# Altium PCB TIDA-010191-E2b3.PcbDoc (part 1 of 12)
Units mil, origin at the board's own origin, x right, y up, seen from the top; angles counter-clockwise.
Board outline 9842.52 x 9842.4 mil, 6 copper layers (Layer 1 - Top Layer, Layer 2 - GND Layer, Layer 3 - Signal, Layer 4 - Signal, Layer 5 - GND, Bottom Layer), stack 59.9 mil thick; 1178 components, 642 nets, 3329 pads, 2967 vias.
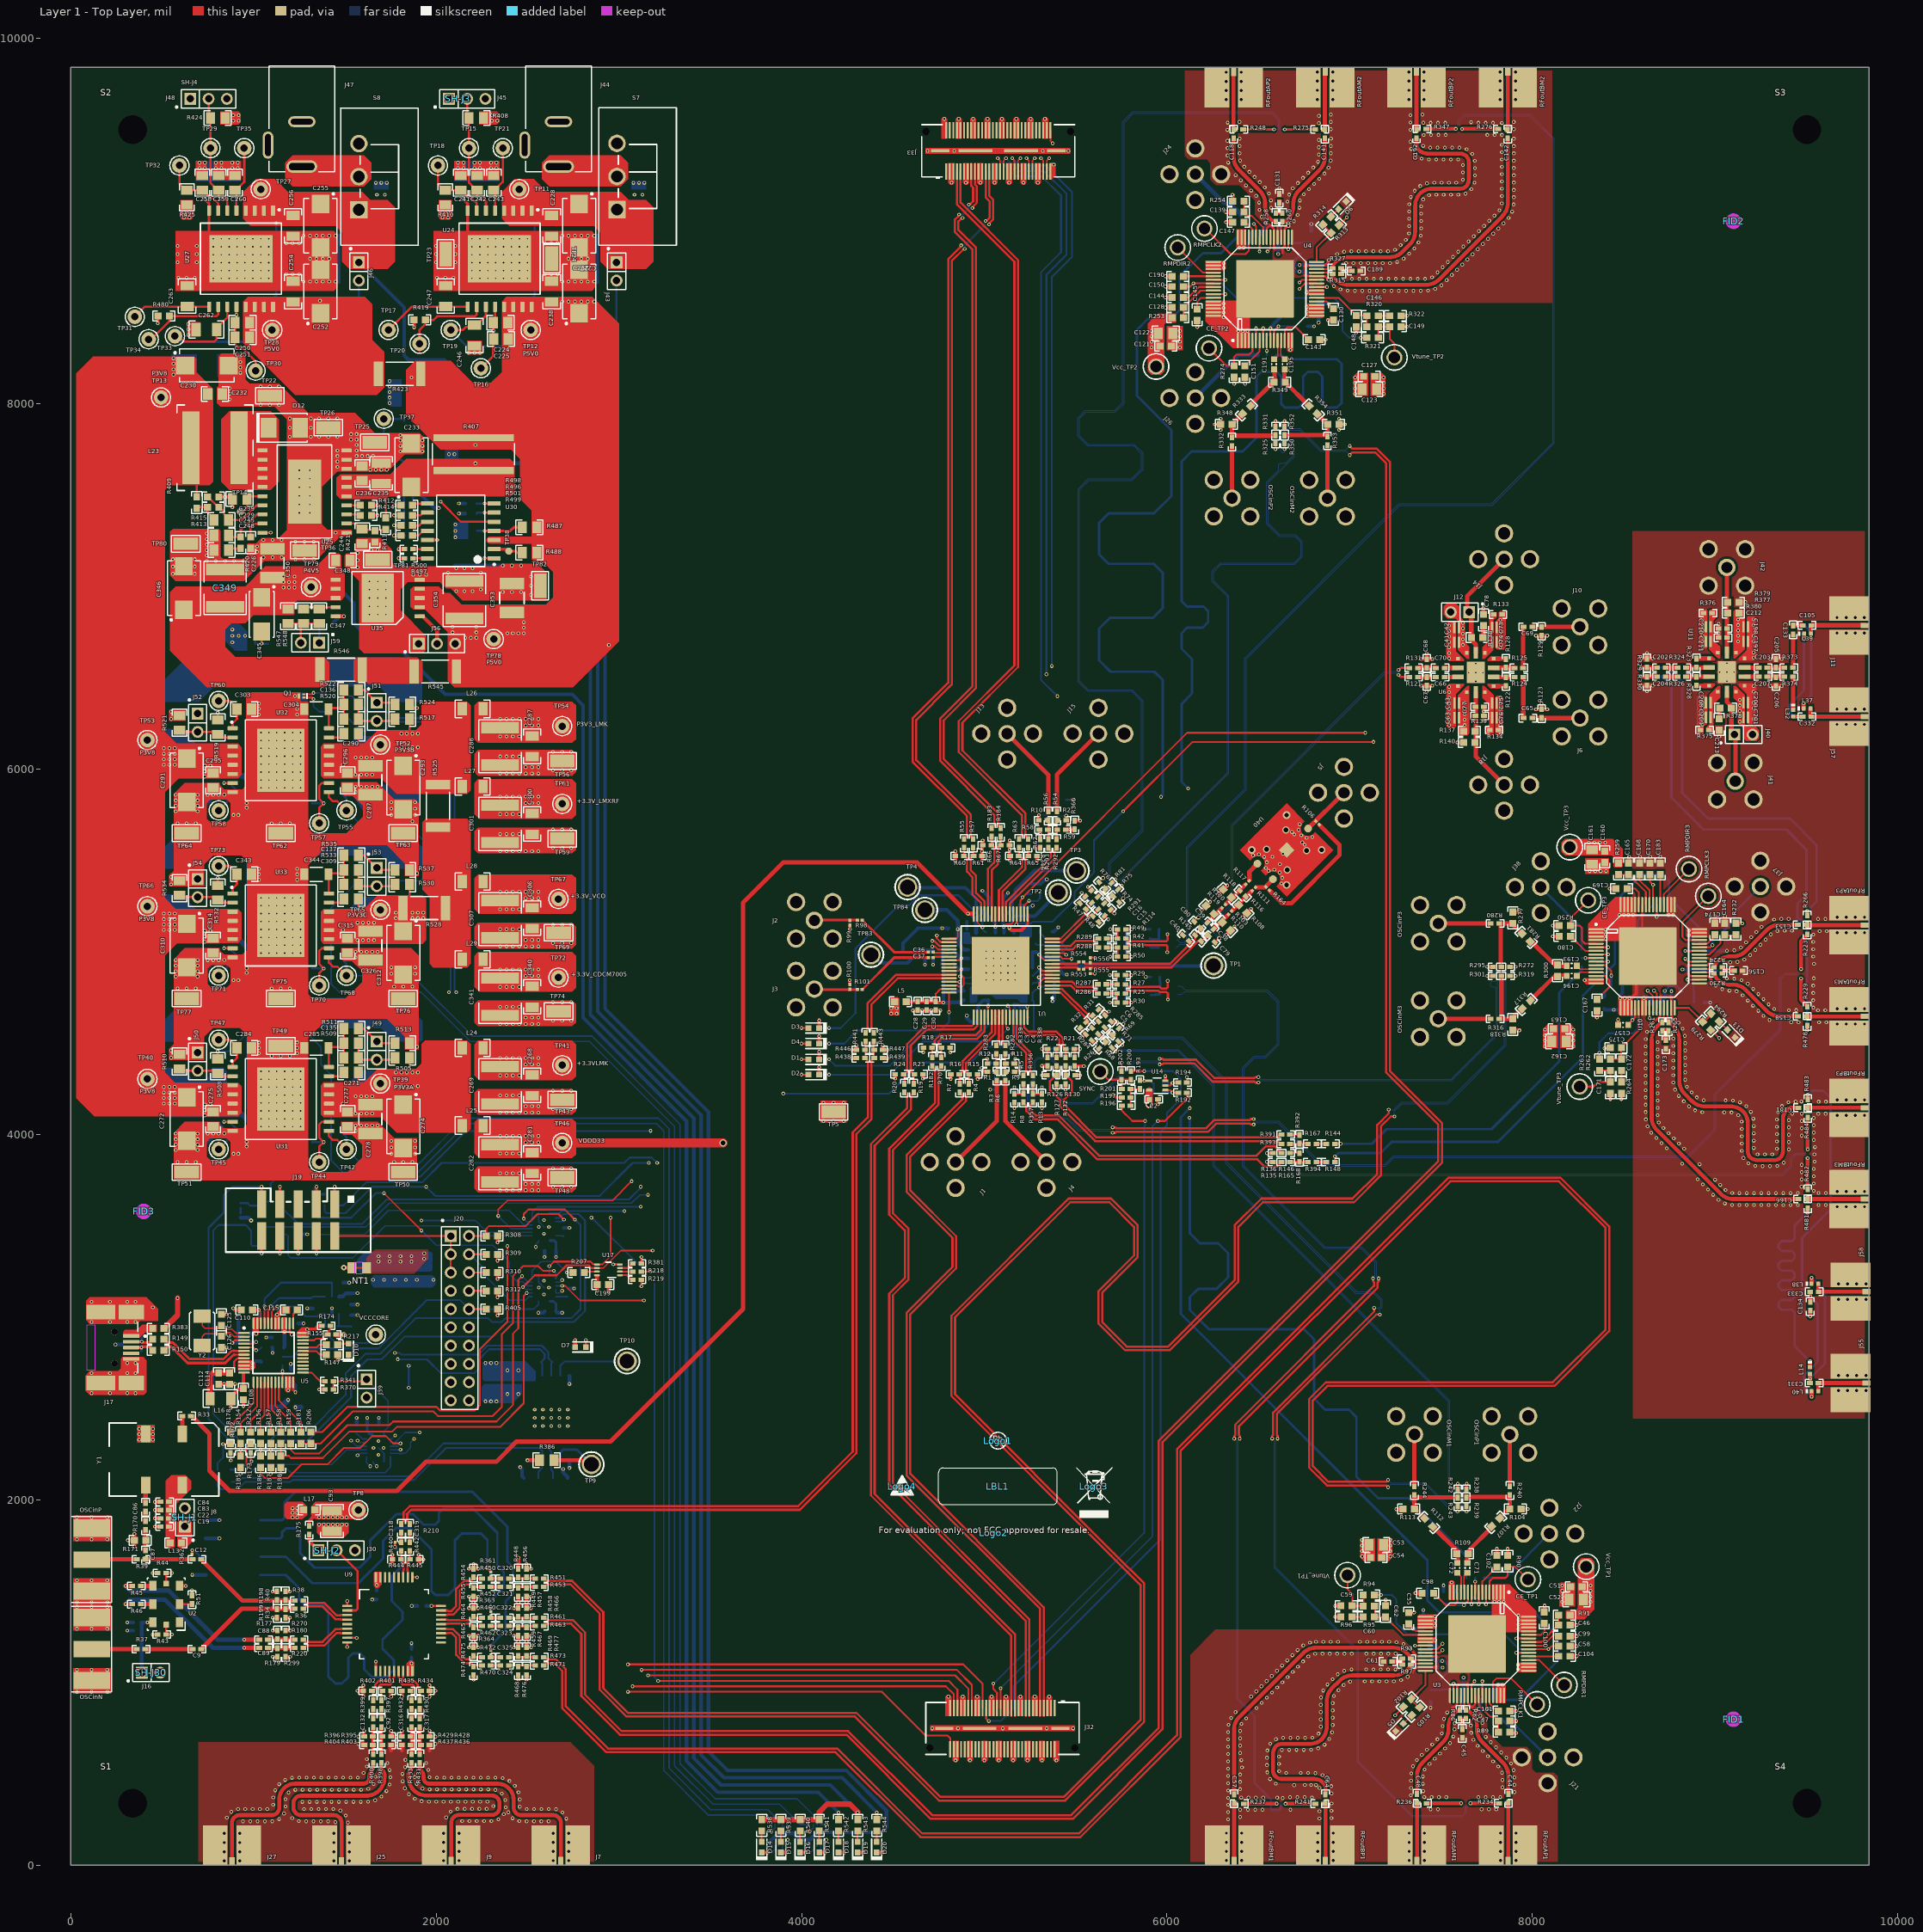
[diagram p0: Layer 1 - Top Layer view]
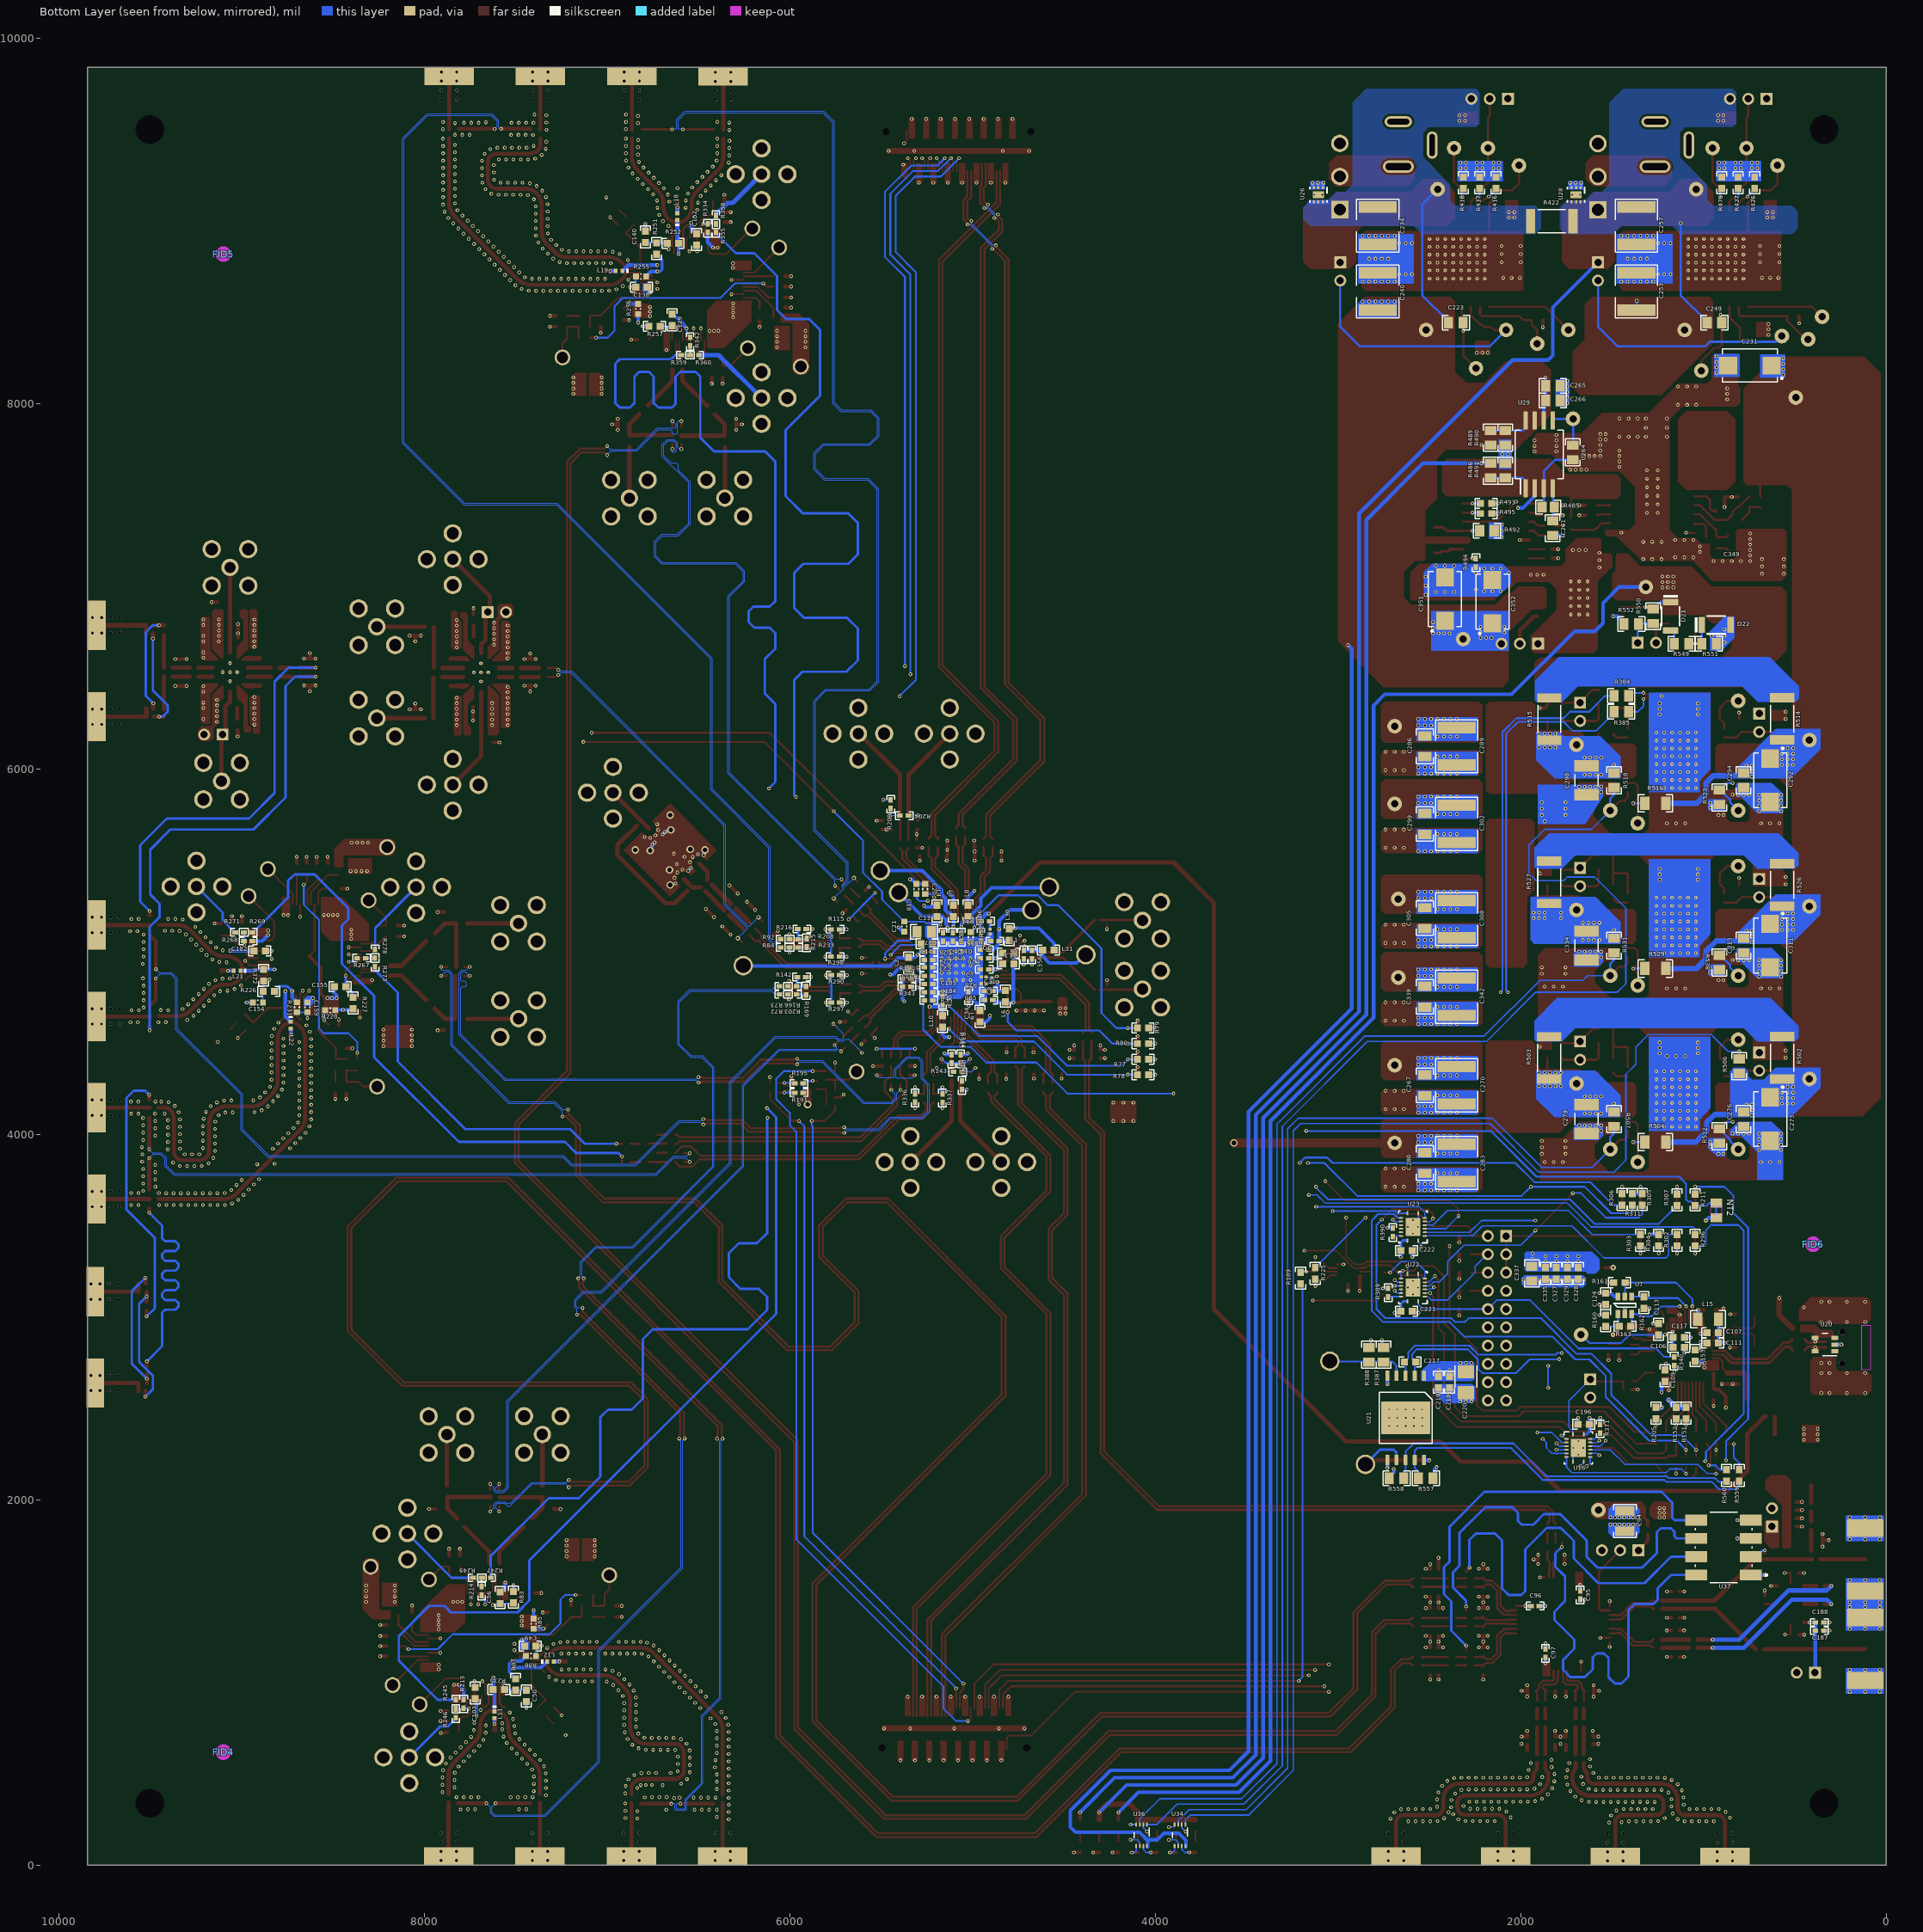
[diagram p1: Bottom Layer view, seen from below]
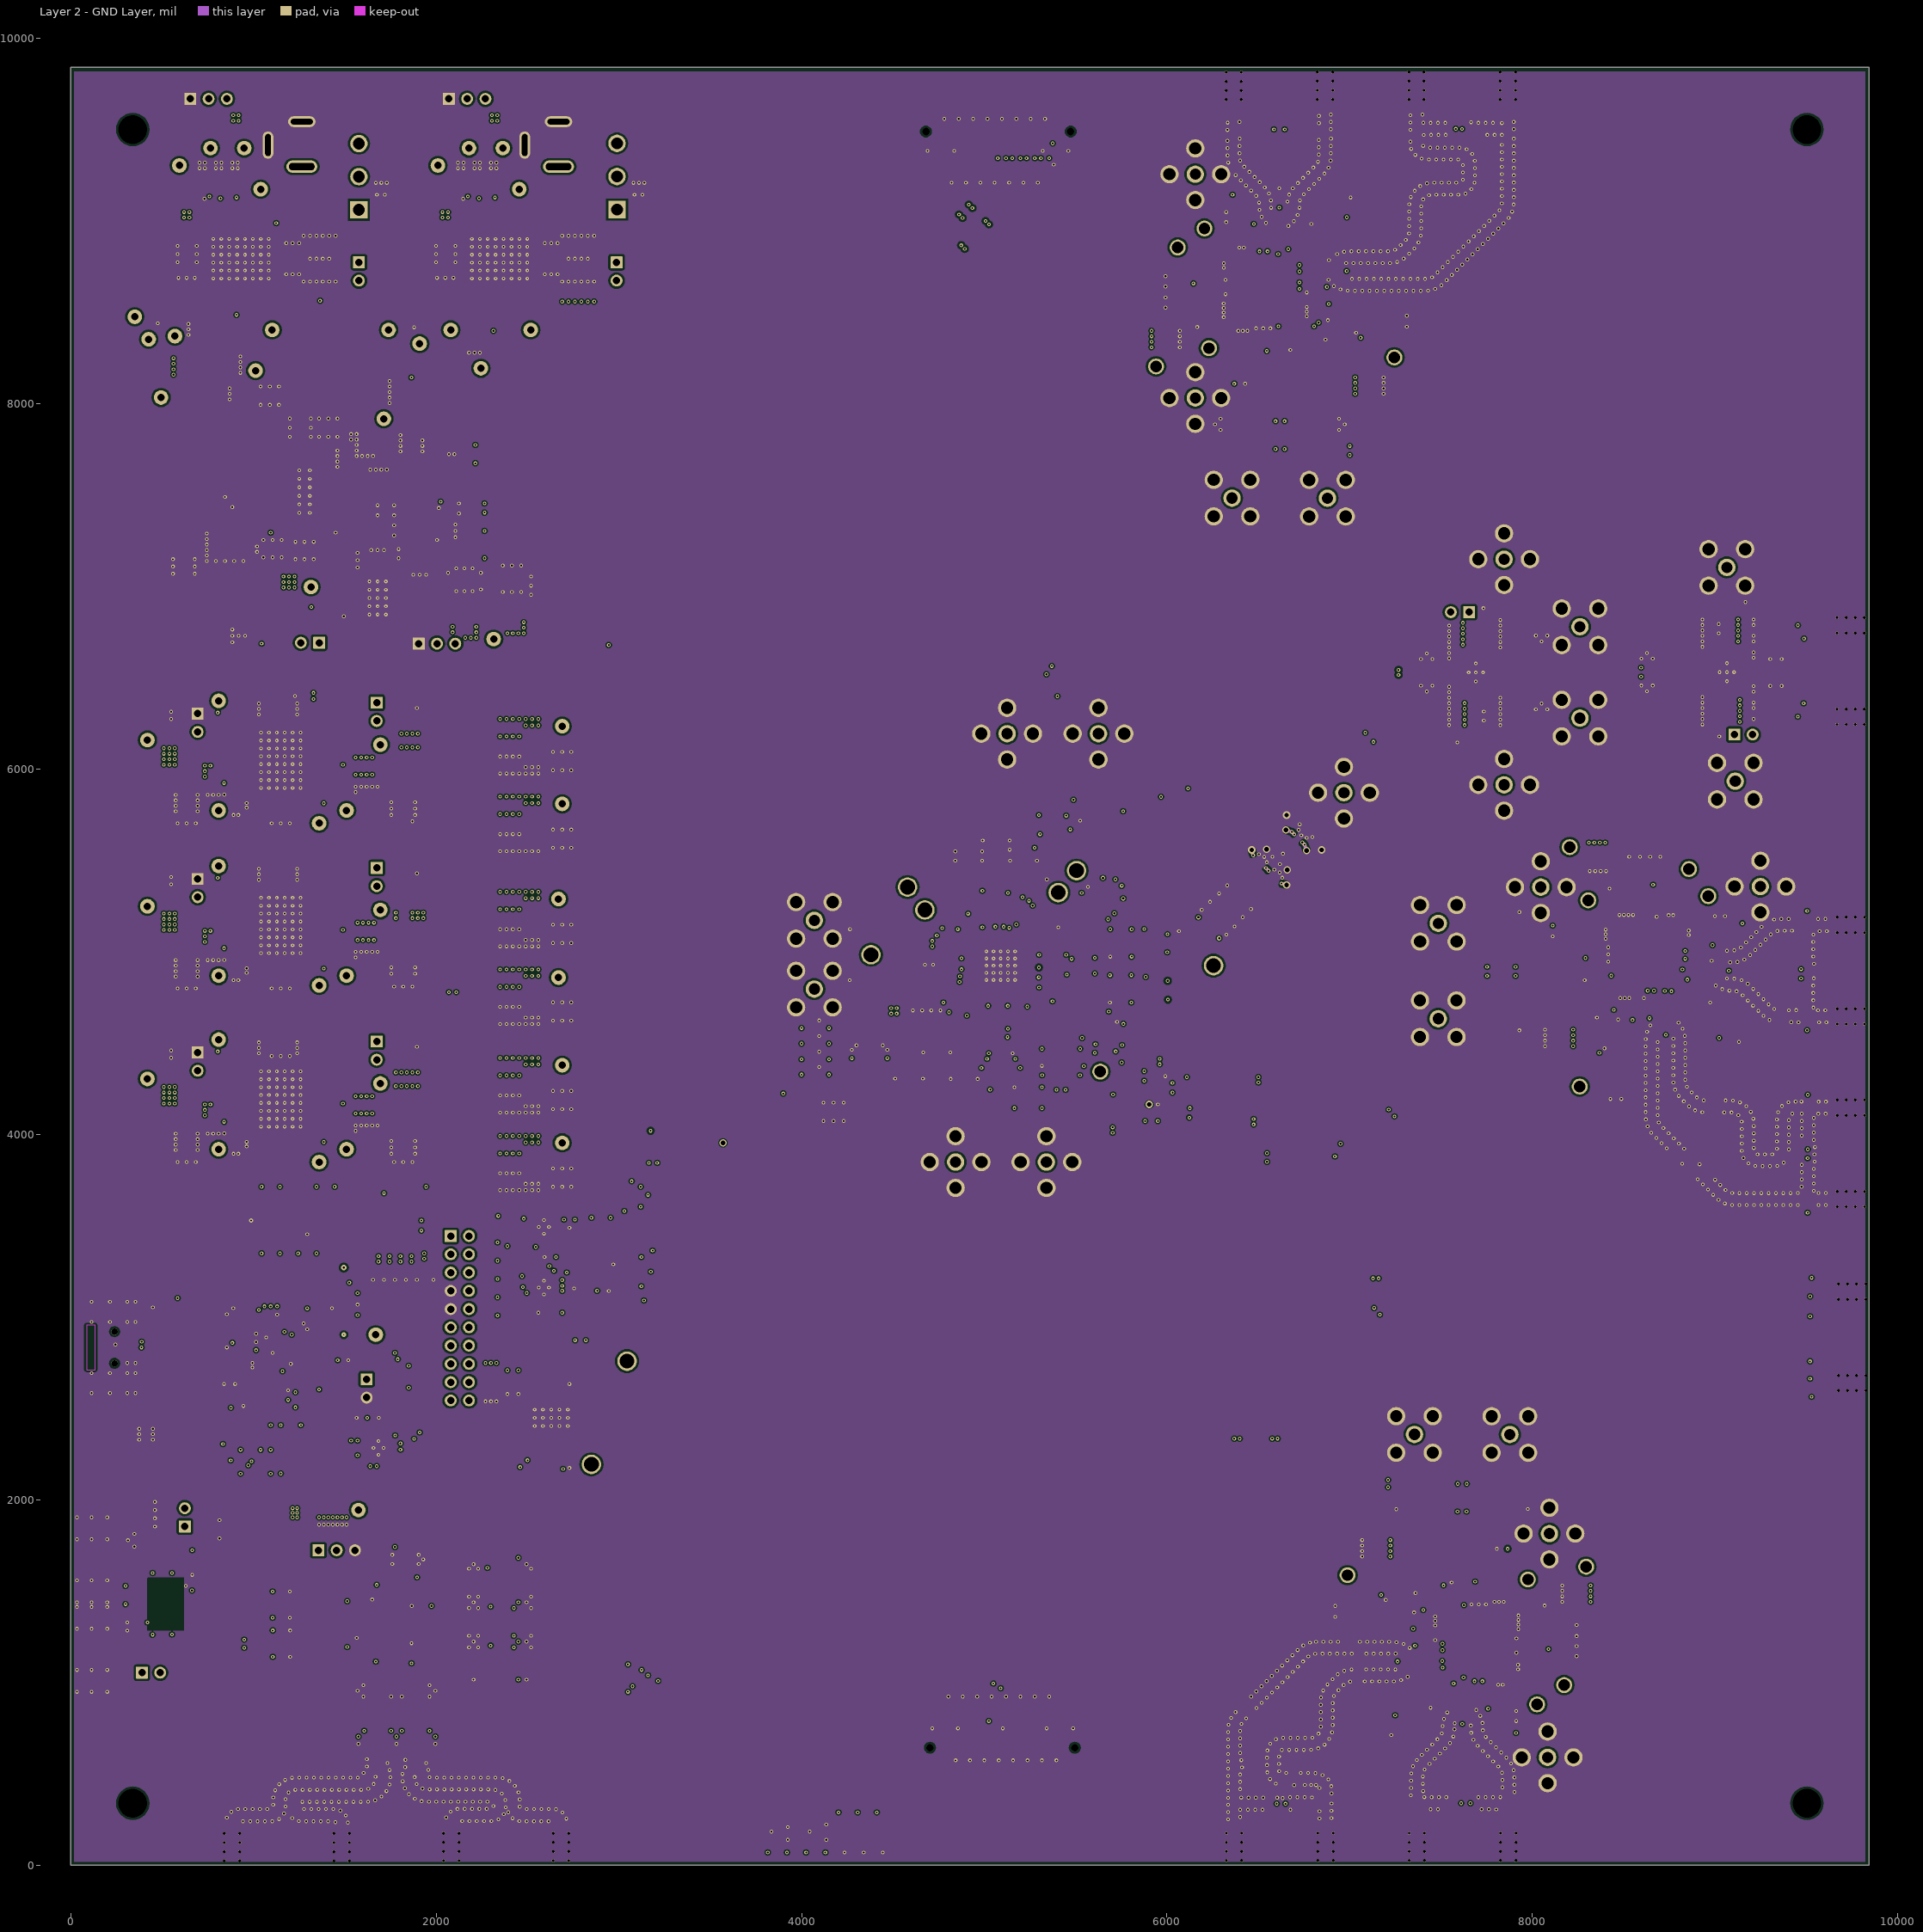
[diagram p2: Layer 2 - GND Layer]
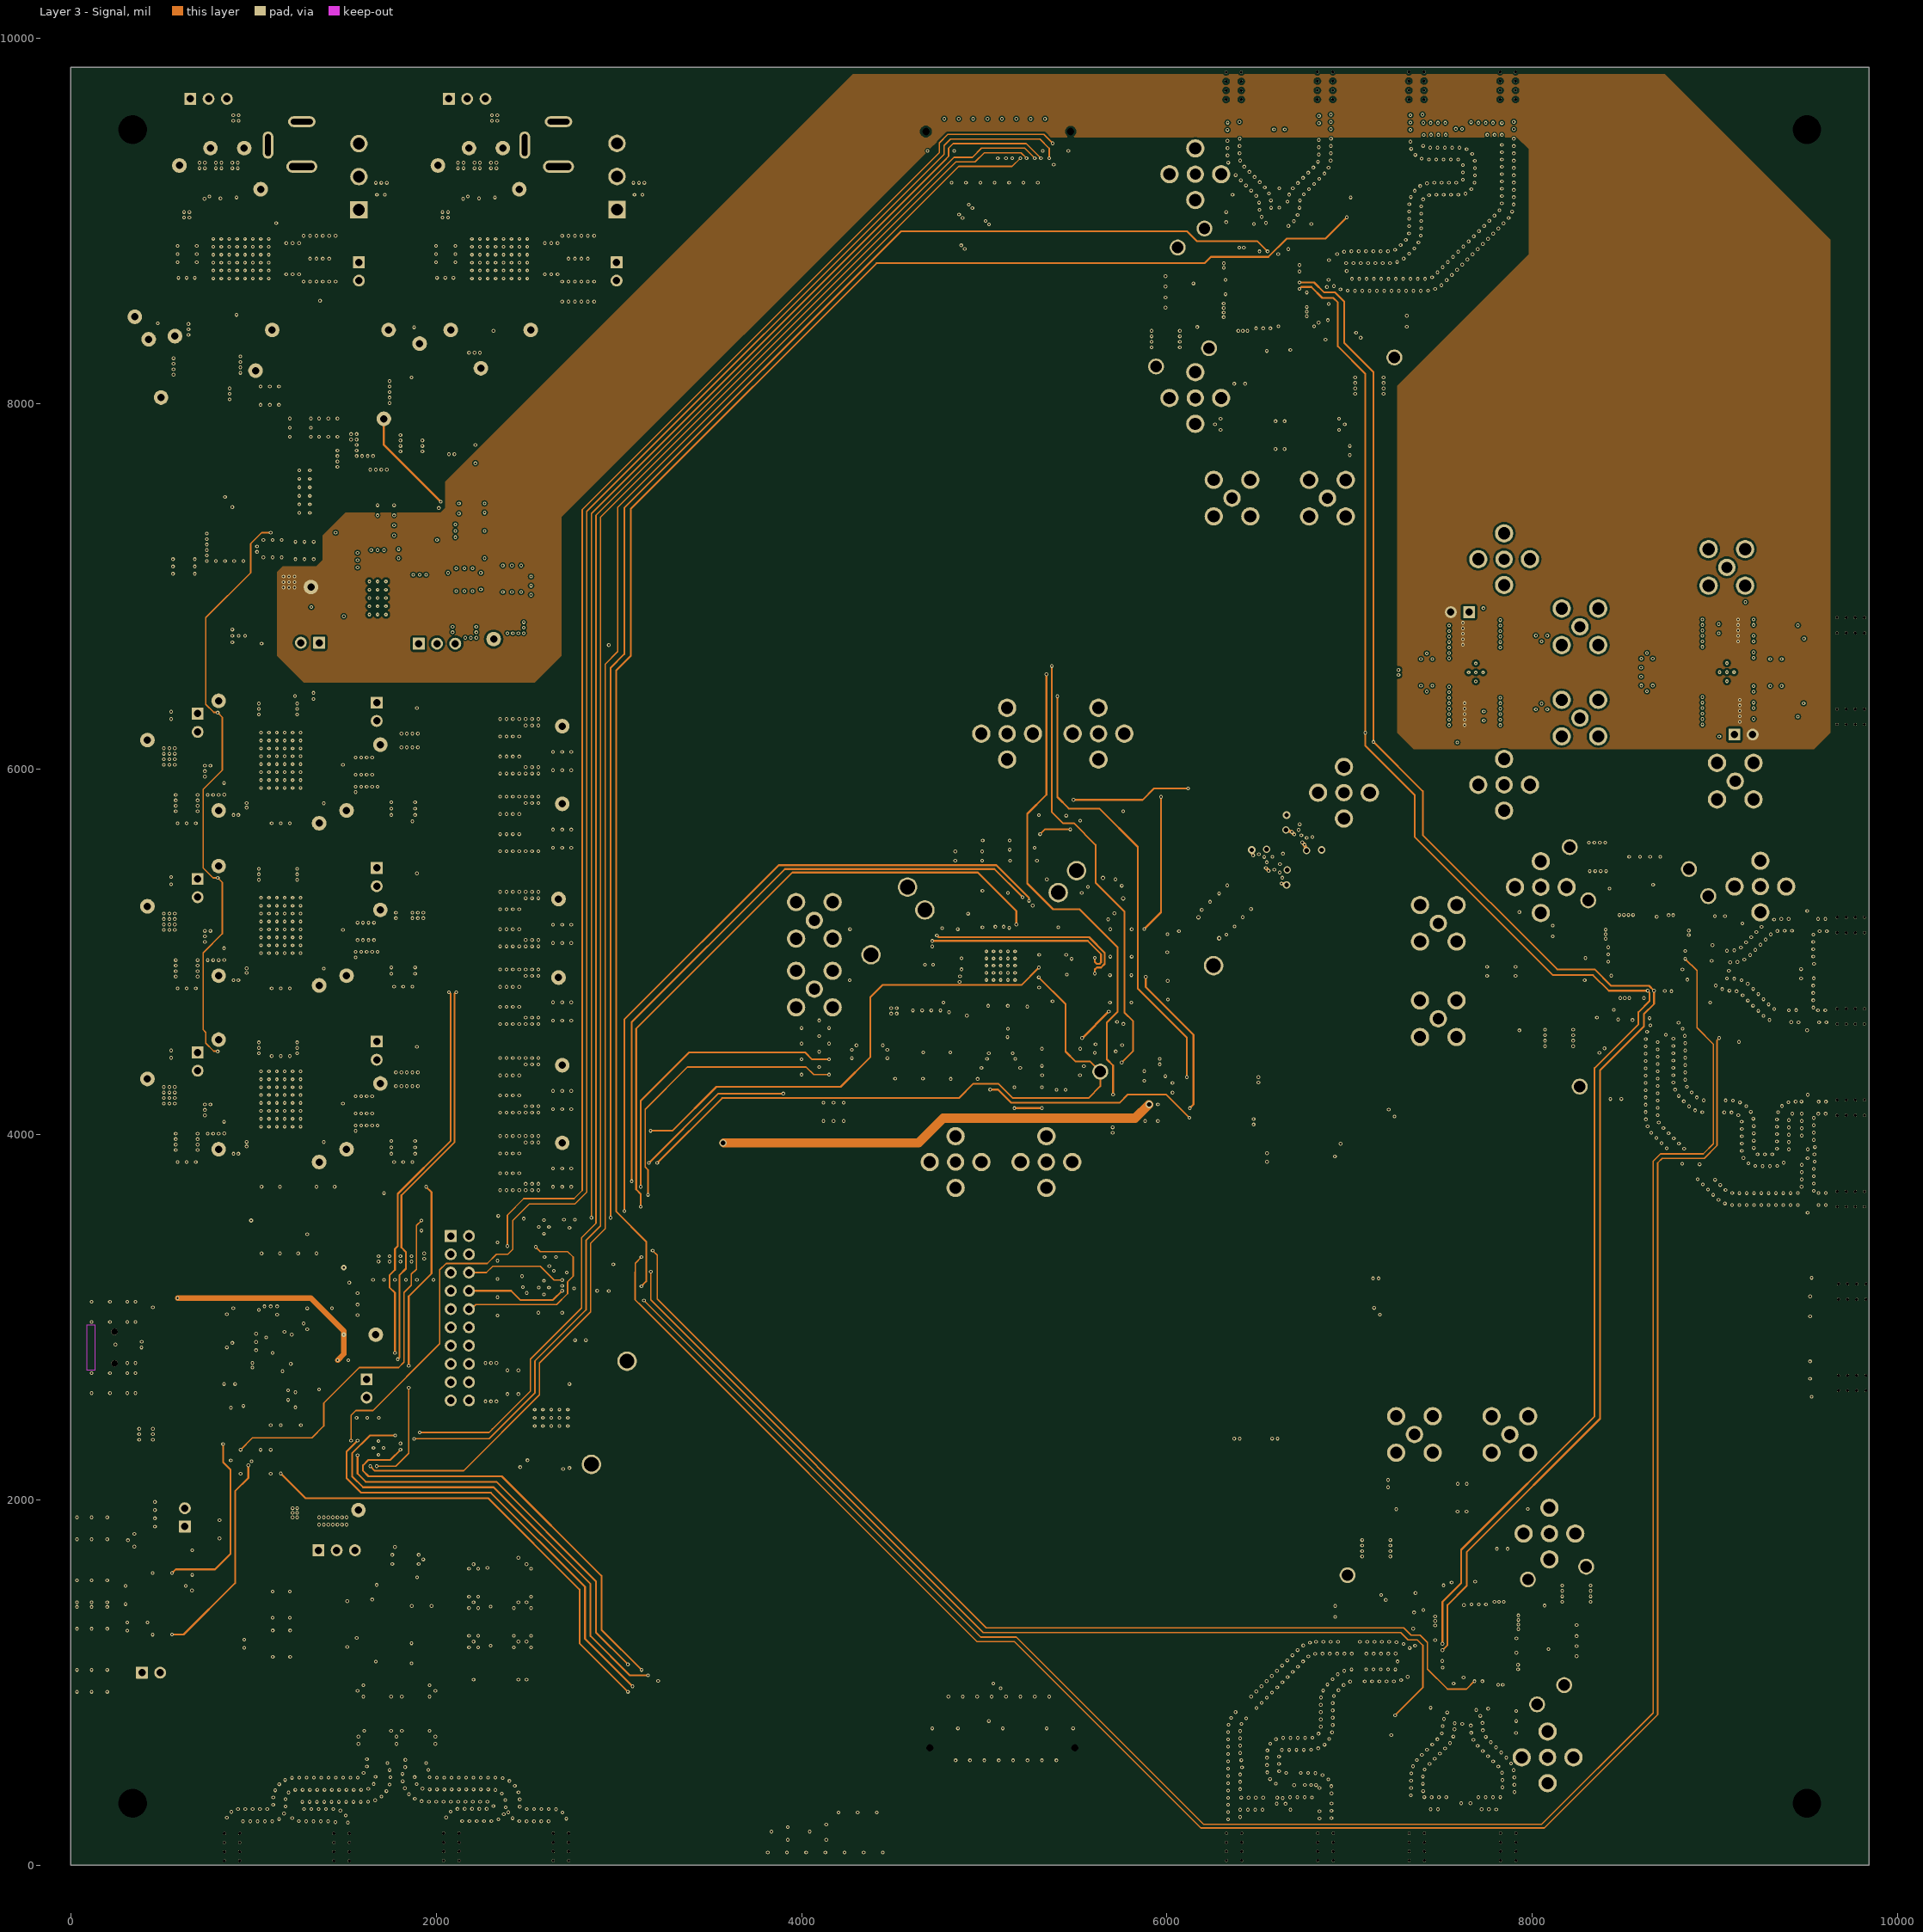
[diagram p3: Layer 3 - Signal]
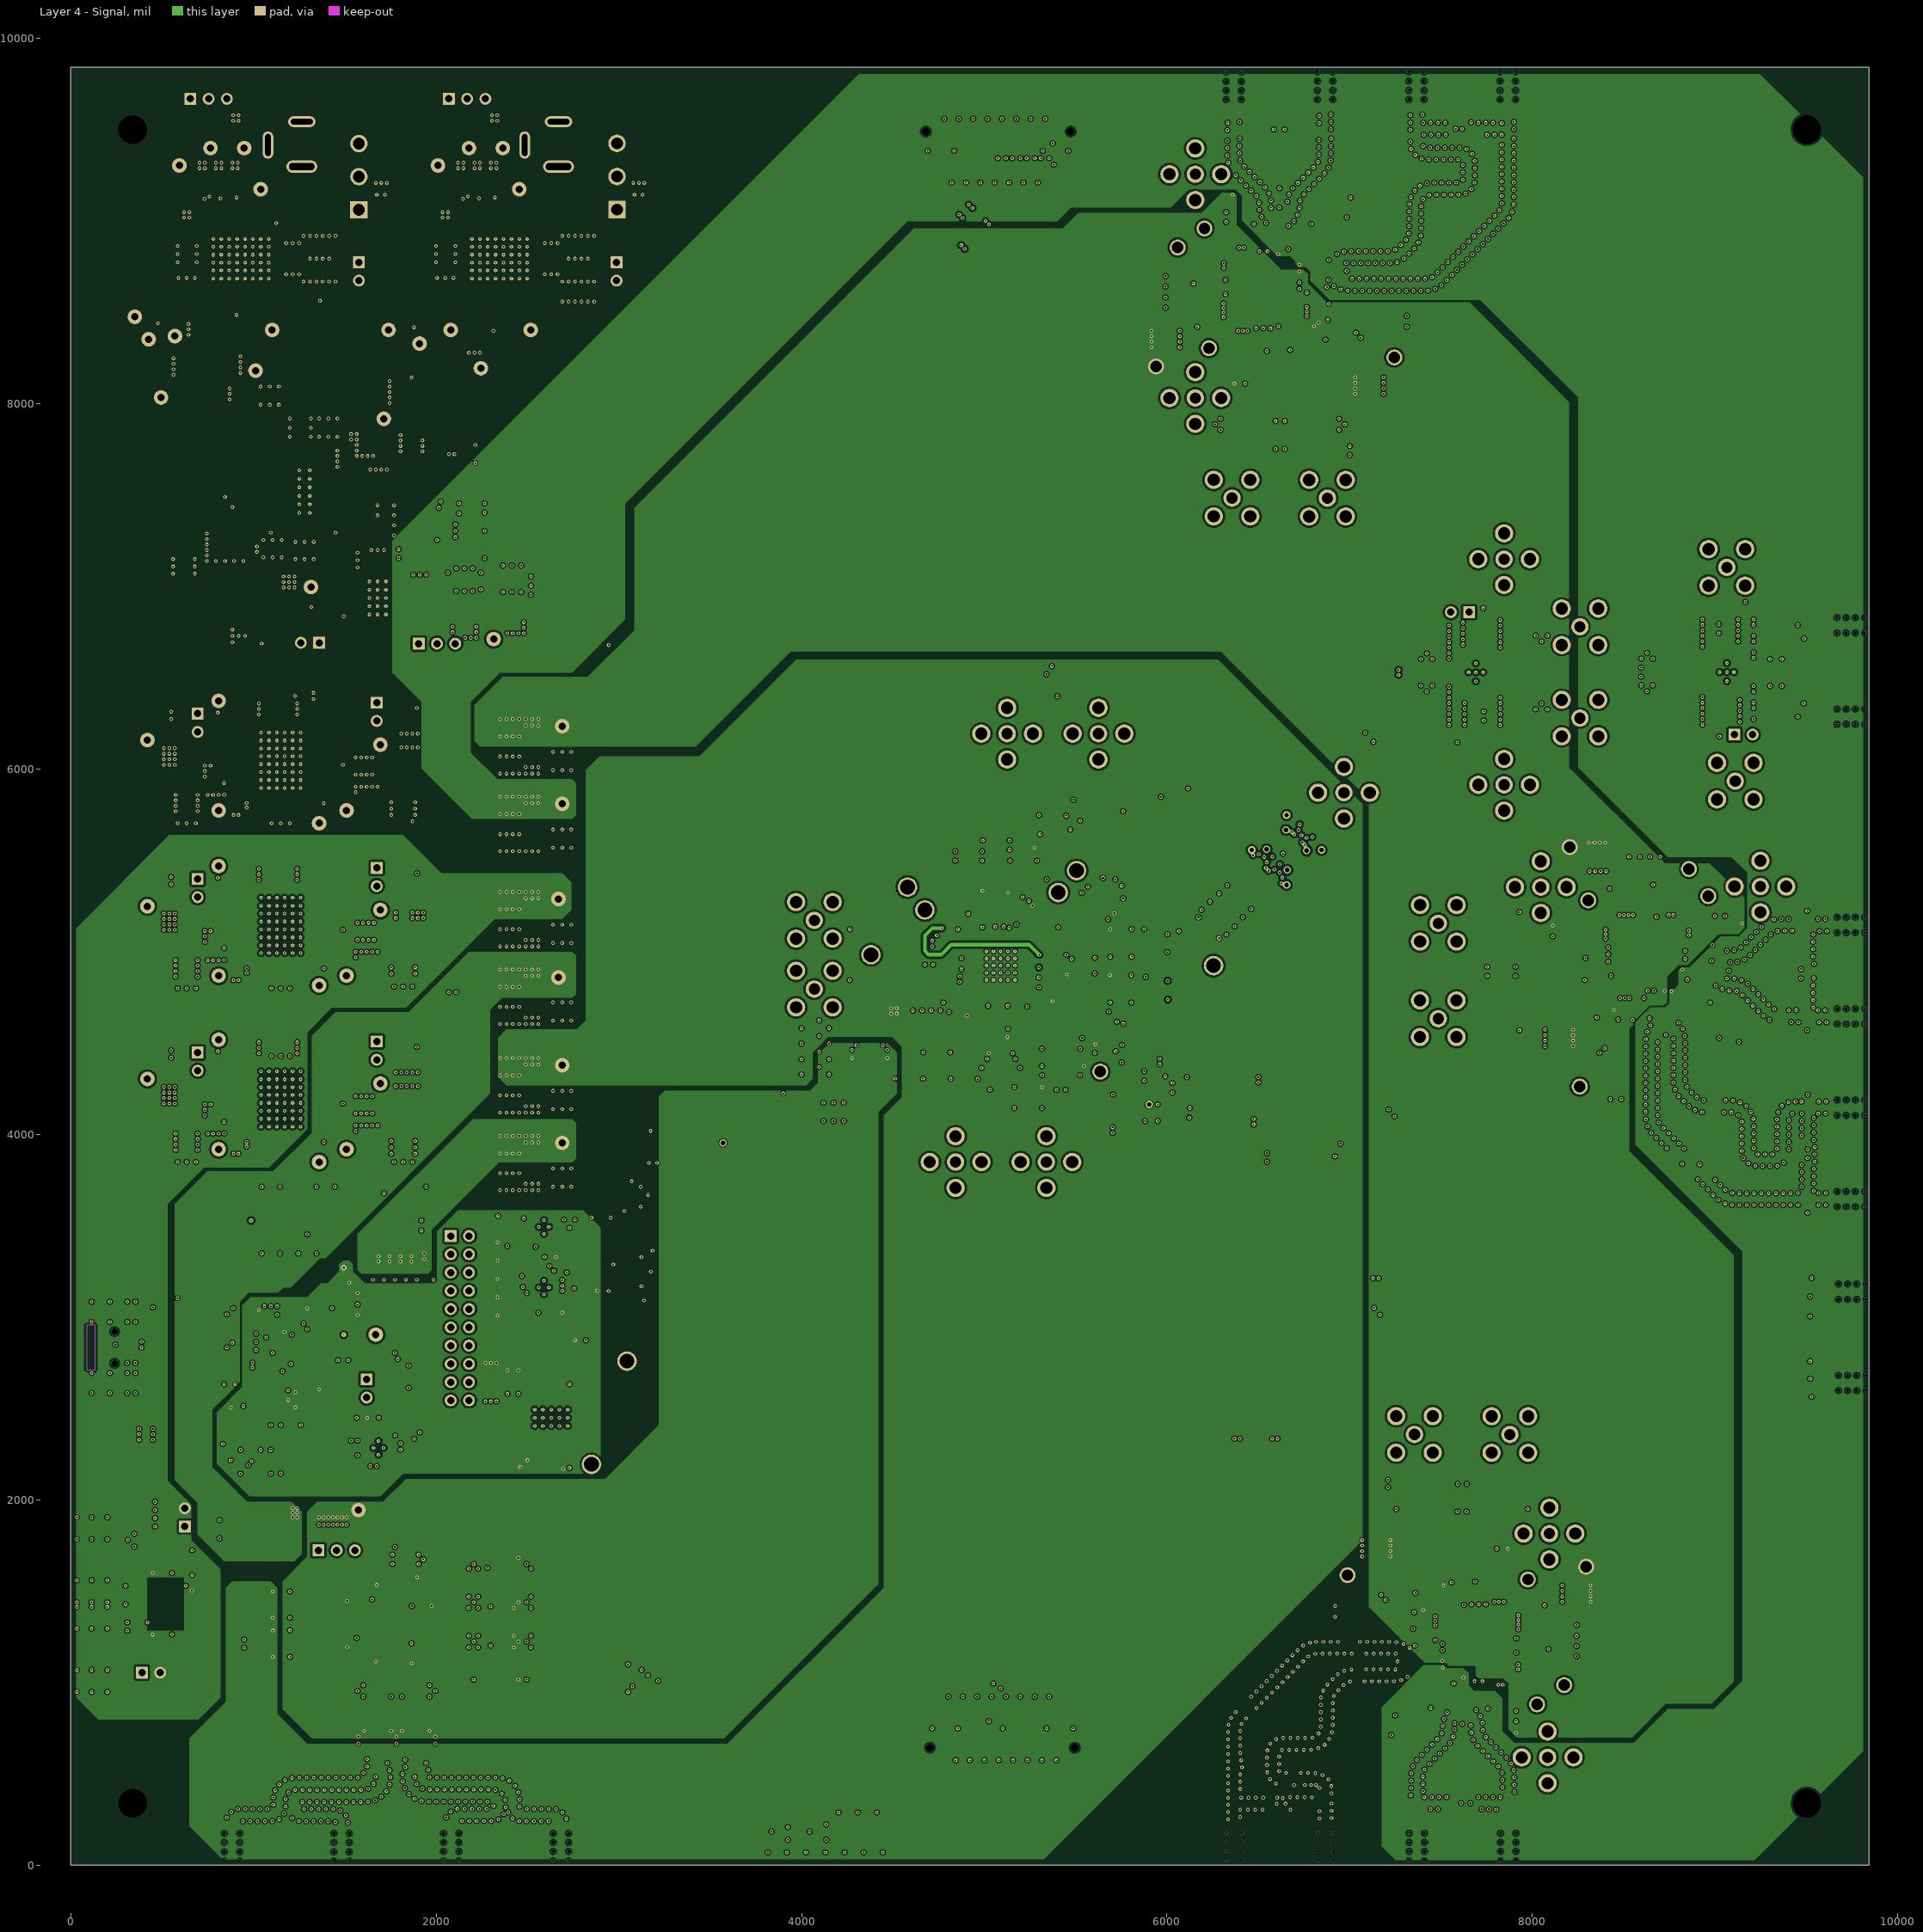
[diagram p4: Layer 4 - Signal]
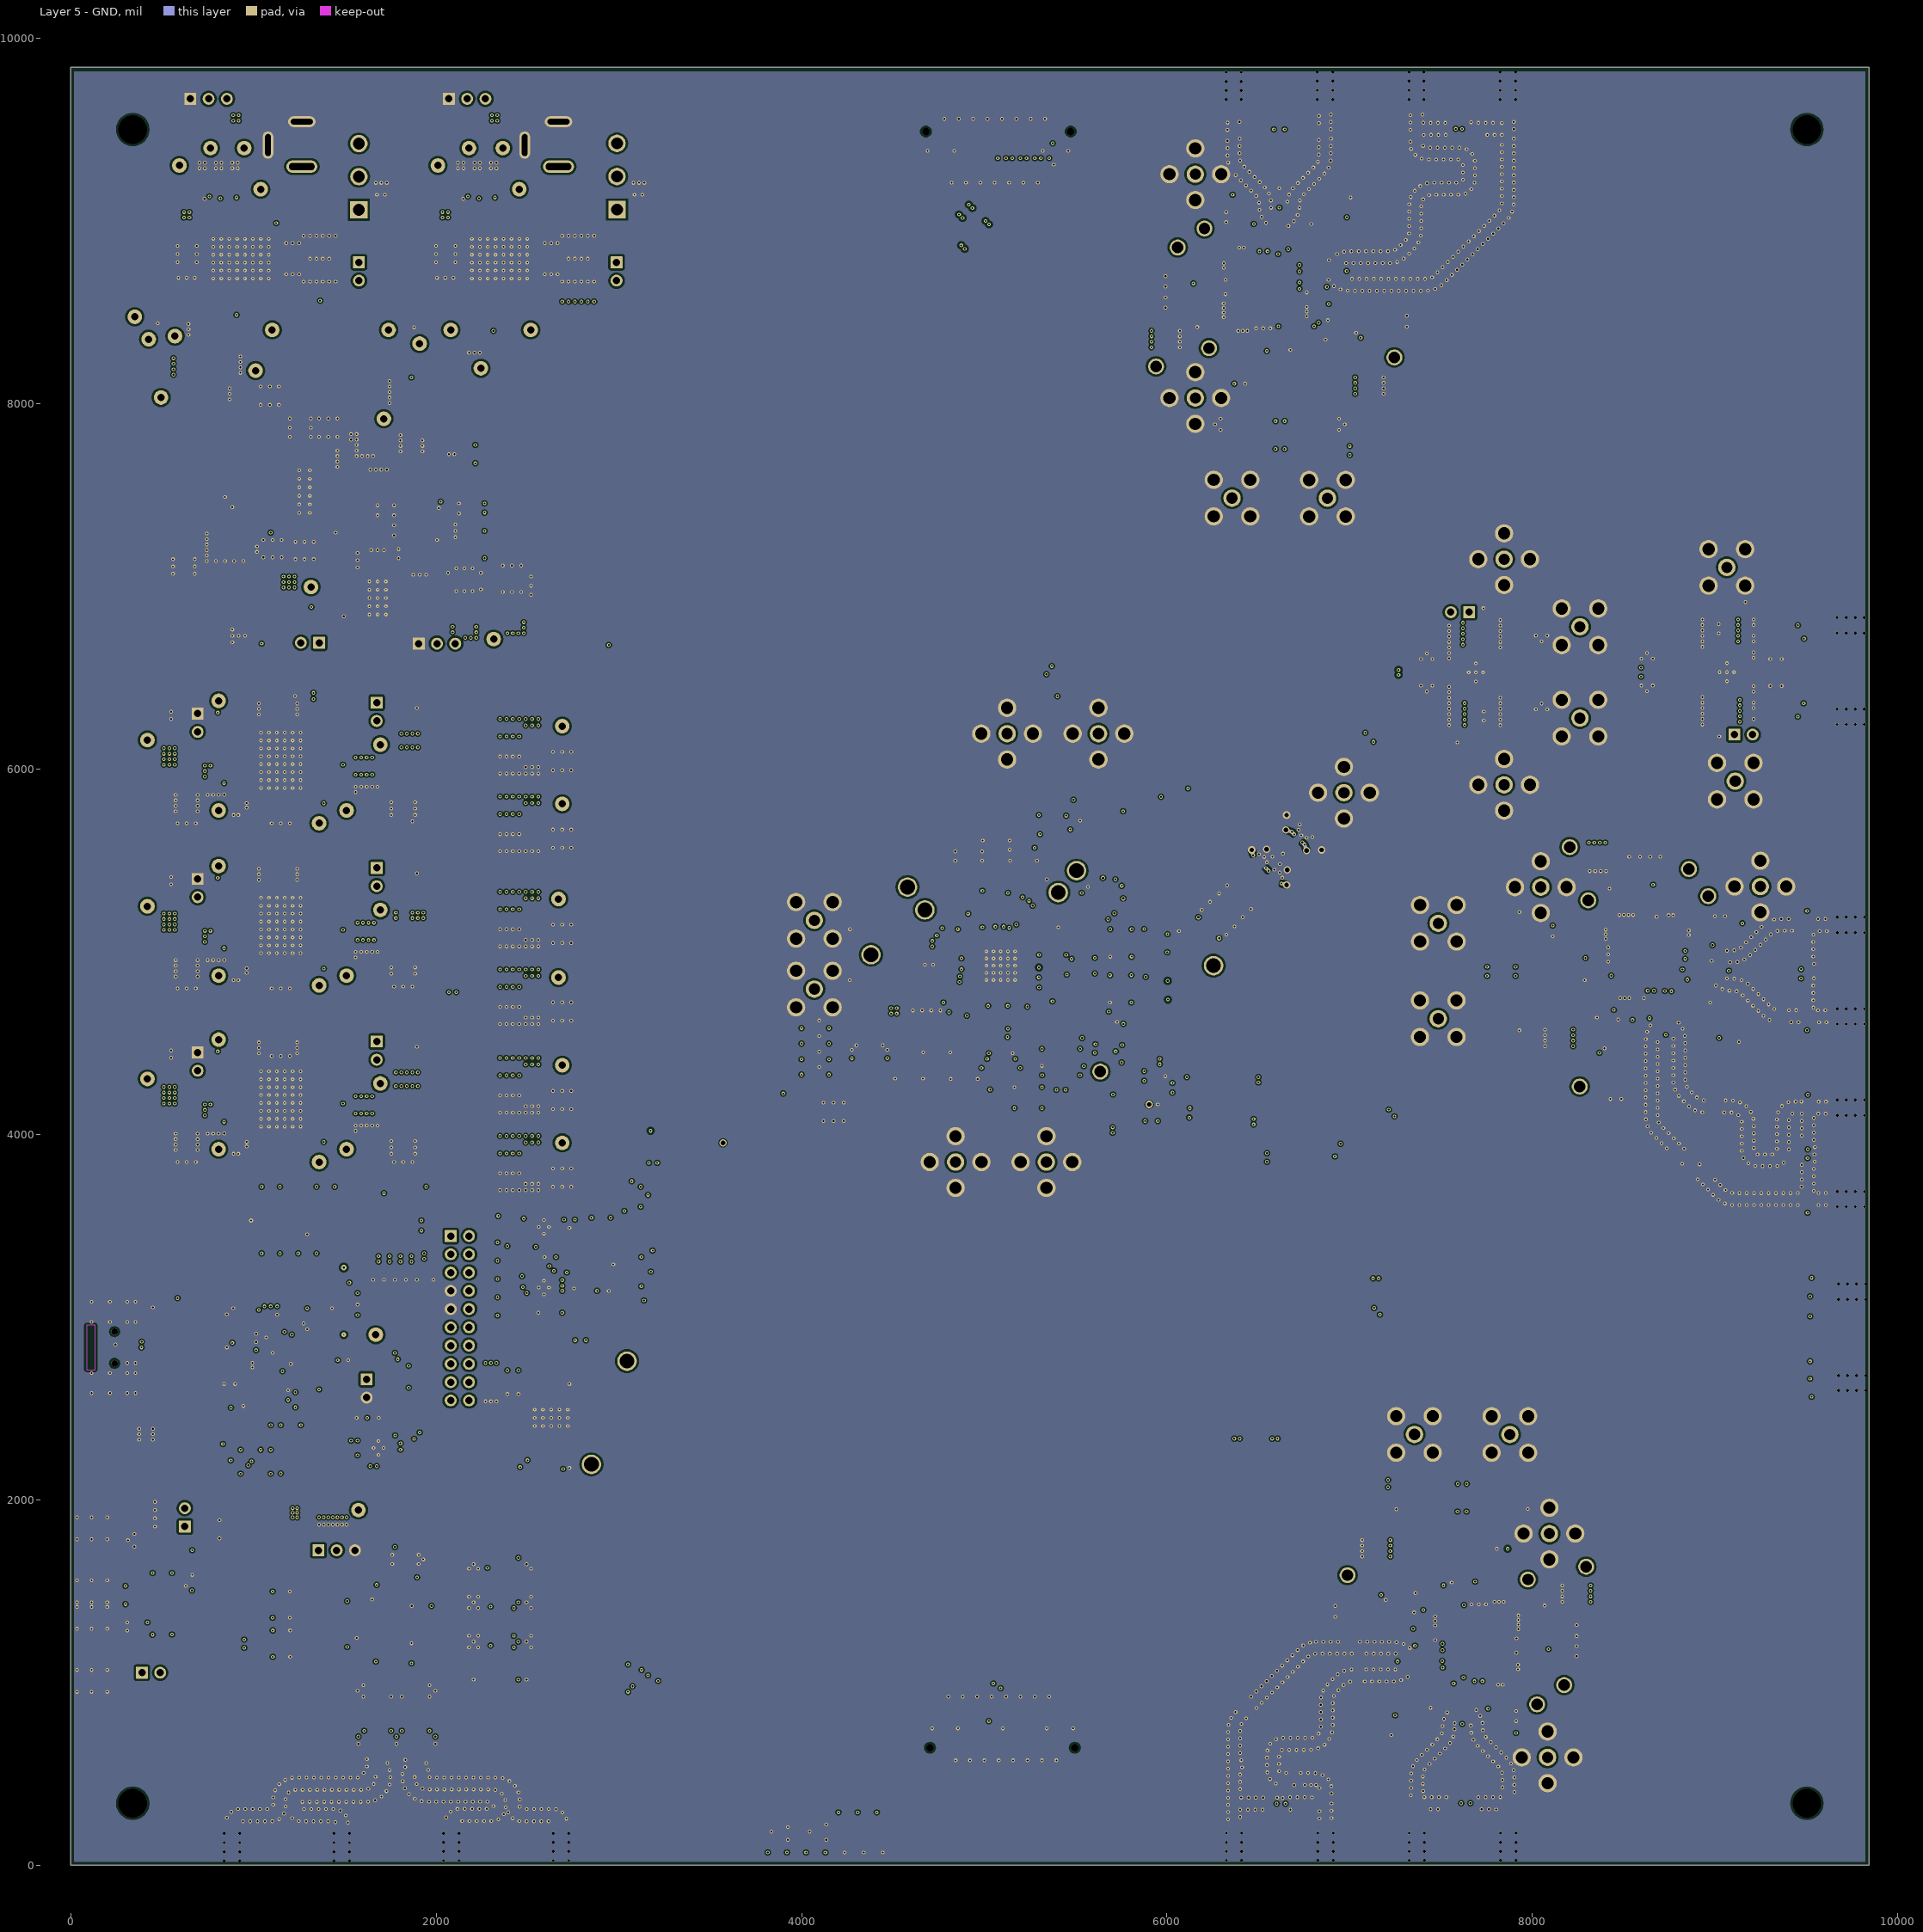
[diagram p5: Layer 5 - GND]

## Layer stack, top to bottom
Top Solder: solder mask 0.4, Solder Resist, Dk 3.5
Layer 1 - Top Layer: signal copper 1.4
Dielectric 1: core 12, Rogers4003C, Dk 4.2
Layer 2 - GND Layer: signal copper 1.4
Dielectric 2: prepreg 8.5, FR4 370, Dk 4.2
Layer 3 - Signal: signal copper 1.4
Dielectric 3: core 14.5, FR4 370, Dk 4.2
Layer 4 - Signal: signal copper 1.4
Dielectric 4: prepreg 8.5, FR4 370, Dk 4.2
Layer 5 - GND: signal copper 1.4
Dielectric 5: core 8, FR4 370, Dk 4.2
Bottom Layer: signal copper 1.4
Bottom Solder: solder mask 0.4, Solder Resist, Dk 3.5

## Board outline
0.09,0.12 0.09,9842.52 9842.61,9842.52 9842.61,0.12

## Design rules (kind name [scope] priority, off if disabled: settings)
AcuteAngle [All] p1: minimum=4.50000000000000E+0001 checktracksonly=FALSE
AssemblyTestPointUsage [All] p1: valid=2
Clearance [All vs not InComponent('FID1') and not InComponent('FID2') and not InComponent('FID3') and not InComponent('FID4') and not InComponent('FID5') and not InComponent('FID6') and not InComponent('U40')] p1: gap=7 ignorepadtopadclearanceinfootprint=TRUE except(3.75: Track-Track; 11.88: Arc-Poly Track-Poly SMDPad-Poly THPad-Poly Via-Poly Fill-Poly Poly-Poly)
ComponentClearance ComponentClearance_1 [HasFootprint('Keystone1573-2')] p1: gap=10 collisioncheckmode=3 verticalgap=10 showdistances=FALSE
ComponentClearance ComponentClearance_Shunt [InComponentClass('Header') vs InComponentClass('Shunt')] p2: gap=0 collisioncheckmode=3 verticalgap=0 showdistances=FALSE
ComponentClearance ComponentClearance_Logo [InComponentClass('Logo')] p3: gap=50 collisioncheckmode=3 verticalgap=10 showdistances=FALSE
ComponentClearance ComponentClearance_ScrewToNut [(HasFootprint('NY PMS 440 0025 PH')) vs (HasFootprint('Keystone_1902C'))] p4: gap=5 collisioncheckmode=3 verticalgap=10 showdistances=FALSE
ComponentClearance ComponentClearance_MountingHoles [InComponentClass('Mounting Holes')] p5: gap=250 collisioncheckmode=3 verticalgap=100000 showdistances=FALSE
ComponentClearance ComponentClearance_SmallPassives [HasFootprint('0201*') or HasFootprint('0402*') or HasFootprint('0508') or HasFootprint('0603*') or HasFootprint('0612') or HasFootprint('0805*') or HasFootprint('0815*') or HasFootprint('0830*') or HasFootprint('1206*') or HasFootprint('1210*') or HasFootprint('1808*') or HasFootprint('1812*') or HasFootprint('1825*') or HasFootprint('2010*') or HasFootprint('2220*') or HasFootprint('2225*') or HasFootprint('2512*') or HasFootprint('2728*') or HasFootprint('3518*') vs HasFootprint('0201*') or HasFootprint('0402*') or HasFootprint('0508') or HasFootprint('0603*') or HasFootprint('0612') or HasFootprint('0805*') or HasFootprint('0815*') or HasFootprint('0830*') or HasFootprint('1206*') or HasFootprint('1210*') or HasFootprint('1808*') or HasFootprint('1812*') or HasFootprint('1825*') or HasFootprint('2010*') or HasFootprint('2220*') or HasFootprint('2225*') or HasFootprint('2512*') or HasFootprint('2728*') or HasFootprint('3518*')] p6: gap=10 collisioncheckmode=3 verticalgap=10 showdistances=FALSE
ComponentClearance ComponentClearance_THtoSMT [IsThruComponent vs IsSMTComponent] p7: gap=40 collisioncheckmode=3 verticalgap=30 showdistances=FALSE
ComponentClearance ComponentClearance_THtoTH [IsThruComponent vs IsThruComponent] p8: gap=40 collisioncheckmode=3 verticalgap=30 showdistances=FALSE
ComponentClearance [All] p9: gap=20 collisioncheckmode=3 verticalgap=10 showdistances=FALSE
DiffPairsRouting DiffPairsRouting_100OHM [InDifferentialPairClass('100ohm')] p1: maxlimit=15 minlimit=4.25 mostfreqgap=8 toplayer_mingap=8 toplayer_minwidth=12 toplayer_maxwidth=12 toplayer_prefwidth=12 midlayer1_mingap=8 midlayer1_maxgap=8 midlayer1_minwidth=8 midlayer1_maxwidth=8 midlayer1_prefwidth=8 midlayer2_mingap=8 midlayer2_maxgap=8 midlayer2_minwidth=8 midlayer2_maxwidth=8 midlayer2_prefwidth=8 midlayer3_mingap=6.25 midlayer3_prefgap=6.25 midlayer3_minwidth=4.75 midlayer3_maxwidth=4.75 midlayer3_prefwidth=4.75 midlayer4_mingap=8 midlayer4_maxgap=8 midlayer4_minwidth=8 midlayer4_maxwidth=8 midlayer4_prefwidth=8 bottomlayer_prefgap=4.25 bottomlayer_minwidth=3.75 bottomlayer_maxwidth=3.75 bottomlayer_prefwidth=3.75 filterlayerstackid={EAC6E6AE-040B-479F-9AA2-99B4E561E951} maxuncoupledlength=500
DiffPairsRouting DiffPair_DiffPairsRouting_USB [InDifferentialPairClass('90ohm')] p2: maxlimit=15 minlimit=5 mostfreqgap=5 toplayer_mingap=7 toplayer_prefgap=7 toplayer_minwidth=8 toplayer_maxwidth=15 toplayer_prefwidth=15 midlayer1_mingap=7 midlayer1_maxgap=7 midlayer1_prefgap=7 midlayer1_minwidth=7 midlayer1_maxwidth=7 midlayer1_prefwidth=7 midlayer2_maxgap=5 midlayer2_minwidth=6.5 midlayer2_maxwidth=6.5 midlayer2_prefwidth=6.5 midlayer3_maxgap=5 midlayer3_minwidth=6.5 midlayer3_maxwidth=6.5 midlayer3_prefwidth=6.5 midlayer4_mingap=7 midlayer4_maxgap=7 midlayer4_prefgap=7 midlayer4_minwidth=7 midlayer4_maxwidth=7 midlayer4_prefwidth=7 bottomlayer_maxgap=5 bottomlayer_minwidth=7 bottomlayer_maxwidth=7 bottomlayer_prefwidth=7 maxuncoupledlength=500
FabricationTestPointUsage TestPointUsage [All] p1: valid=2 allowmultiple=FALSE
FabricationTestpoint Testpoint [All] p1: side=3 testpointundercomponent=TRUE minsize=40 maxsize=100 preferedsize=60 minholesize=0 maxholesize=40 preferedholesize=32 testpointgrid=1 allowsidetop=TRUE allowsidebottom=TRUE usegrid=TRUE gridtolerance=0.01
FanoutControl Fanout_LCC [IsLCC] p1: bgadir=Out bgaviamode=Centered fanoutstyle=Auto fanoutdirection=Alternating viagrid=1 // Fanout_LCC (Default Rule)
FanoutControl Fanout_BGA [IsBGA] p2: bgadir=Out bgaviamode=Centered fanoutstyle=Auto fanoutdirection=Alternating viagrid=1 // Fanout_BGA (Default Rule)
FanoutControl Fanout_Default [All] p4: bgadir=Out bgaviamode=Centered fanoutstyle=Auto fanoutdirection=Alternating viagrid=1 // Fanout_Default (Default Rule)
FanoutControl Fanout_Small [(CompPinCount < 5)] p5: bgadir=Out bgaviamode=Centered fanoutstyle=Auto fanoutdirection=OutThenIn viagrid=1 // Fanout_Small (Default Rule)
HoleSize [All] p1: absolutevalues=TRUE maxlimit=251 minlimit=7.87 maxpercent=80.000 minpercent=20.000
HoleToHoleClearance [All vs not InComponent('U40')] p1: gap=10 allowstackedmicrovias=TRUE
MatchedLengths u37_to_buffer_con [InNetClass('u37_buffer_con')] p1: tolerance=10 checknetsindiffpair=FALSE checkdiffpairvsdiffpair=TRUE checkxsignals=TRUE checkothers=TRUE
MatchedLengths LMK_LMX_DCLK [InxSignalClass('LMK_LMX_DCLK')] p2: tolerance=5 checknetsindiffpair=FALSE checkdiffpairvsdiffpair=TRUE checkxsignals=TRUE checkothers=TRUE
MatchedLengths LMK04832_FPGA [InxSignalClass('LMK04832_FPGA')] p3: tolerance=5 checknetsindiffpair=FALSE checkdiffpairvsdiffpair=TRUE checkxsignals=TRUE checkothers=TRUE
MatchedLengths FPGA_JESD [InxSignalClass('FPGA_JESD')] p4: tolerance=5 checknetsindiffpair=FALSE checkdiffpairvsdiffpair=TRUE checkxsignals=TRUE checkothers=TRUE
MatchedLengths DiffPair_MatchedLengths [InDifferentialPair ('BCLK')] p5: tolerance=1000 checknetsindiffpair=TRUE checkdiffpairvsdiffpair=FALSE checkxsignals=FALSE checkothers=FALSE
MinimumAnnularRing MinimumAnnularRing_ThermalPadVias [IsVia and InAnyComponent] p1: minimumring=5
MinimumAnnularRing [All] p2: minimumring=5
MinimumSolderMaskSliver MinimumSolderMaskSliver_Logo [InComponentClass('Logo') vs InComponentClass('Logo')] p1: minsoldermaskwidth=0.7
MinimumSolderMaskSliver [All] p2: minsoldermaskwidth=3.94
PlaneConnect [All] p1: planeconnectstyle=Relief reliefexpansion=10 reliefentries=4 reliefconductorwidth=10 reliefairgap=10
PolygonConnect [All] p1: connectstyle=Direct reliefconductorwidth=20 reliefentries=4 polygonreliefangle="90 Angle" airgapwidth=15
RoutingVias ThermalPadVias [IsVia and InAnyComponent] p1: holewidth=7.87 width=19.68 viastyle="Through Hole" minholewidth=7.87 minwidth=19.68 maxholewidth=25 maxwidth=42
RoutingVias [All] p2: holewidth=12 width=24 viastyle="Through Hole" minholewidth=7.87 minwidth=19.68 maxholewidth=26 maxwidth=42
SMDEntry [All] p1: side=TRUE corner=TRUE anyangle=FALSE
SMDToCorner [All] p1: distance=30000
SilkToSilkClearance [All] p1: silktosilkclearance=5
SilkToSolderMaskClearance SilkscreenOverComponentPads [IsPad] p1: minsilkscreentomaskgap=5 clearancetoexposedcopper=TRUE
SolderMaskExpansion [All] p1: expansion=2.5 istentingtop=FALSE
Width Width_PWR [InNetClass('PWR')] p1: maxlimit=100 minlimit=10 preferedwidth=20
Width [All] p2: maxlimit=100 minlimit=4.25 preferedwidth=10 toplayer_prefwidth=24 bottomlayer_prefwidth=13.5 minimp=50.000000 maximp=50.000000 favimp=50.000000 checkconnectedcopper=TRUE
15 further rules are at their usual default settings.

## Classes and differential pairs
net class NT2_Nets: GND IOVLVL
net class NT1_Nets: VDDD33 VREGIN
net class Y2_Nets: OSCI OSCO
net class Y1_Nets: GND NetC19_2 NetC86_1 NetR33_1
net class Vtune_TP3_Nets: NetC171_1
net class Vtune_TP2_Nets: NetC149_1
net class Vtune_TP1_Nets: NetC59_1
net class VCCCORE_Nets: NetC113_2
net class Vcc_TP3_Nets: P3V3_LMX
net class Vcc_TP2_Nets: P3V3_LMX
net class Vcc_TP1_Nets: P3V3_LMX
net class U40_Nets: GND NetJ5_1 NetR111_1 NetR117_1
net class U37_Nets: GND NetR210_2 NetR361_2 NetR362_2 NetR363_2 NetR364_2
net class U36_Nets: GND NetD16_2 NetD17_2 P5V0 PWRGD_LDO_B PWRGD_LDO_C
net class U35_Nets: GND NetC347_2 NetJ56_2 P4V5 P5V0
net class U34_Nets: GND NetD14_2 NetD15_2 P5V0 PWRGD PWRGD_LDO_A
net class U33_Nets: GND NetC137_2 NetC309_1 NetC343_1 NetJ54_2 NetR529_1 NetR536_2 P3V3C P3V8 PWRGD_LDO_C
net class U32_Nets: GND NetC136_2 NetC290_1 NetC303_1 NetJ52_2 NetR516_1 NetR523_2 P3V3B P3V8 PWRGD_LDO_B
net class U31_Nets: GND NetC135_2 NetC271_1 NetC284_1 NetJ50_2 NetR504_1 NetR512_2 P3V3A P3V8 PWRGD_LDO_A
net class U30_Nets: GND NetC264_2 NetR487_2 NetR488_2 NetR493_2 NetR494_2 NetR495_2 NetR496_2 NetR497_2 NetR498_2 NetR499_2 NetR500_2 NetR501_2 P5V0
net class U29_Nets: GND NetC261_1 NetC264_1 NetC264_2 NetR486_2 NetR489_2 NetU29_7 P5V0
net class U28_Nets: GND VIN_P5V0_Redundant
net class U27_Nets: GND NetC249_1 NetC250_1 NetC258_1 NetC259_1 NetC260_1 NetC262_2 NetC263_2 NetR480_2 VIN_P5V0_Redundant
net class U26_Nets: GND VIN_P5V0
net class U25_Nets: GND NetC226_2 NetC239_1 NetC244_1 NetC245_1 NetD12_1 NetR412_1 NetR414_1 P5V0* PWRGD VSENSE
net class U24_Nets: GND NetC223_1 NetC241_1 NetC242_1 NetC243_1 NetC246_2 NetC247_2 NetR419_2 P5V0 VIN_P5V0
net class U23_Nets: ACBUS0 ELMK_SCK ELMK_SDIO GND ILMK04832-SP_CSb ILMK_LMX_CLK ILMK_LMX_DATA LMK04832-SP_CSb LMK_LMX_CLK LMK_LMX_DATA LMK_SCSb NetR390_2 NetU23_12 NetU23_13 NetU23_14 VREGIN
net class U22_Nets: ACBUS0 ELMK_SDO GND ILMX1_CSb ILMX2_CSb ILMX_SDO LMX1_CSb LMX1_SCSb LMX2_CSb LMX2_SCSb LMX3_CSb LMX3_SCSb LMX_SDO NetR389_2 VREGIN
net class U21_Nets: GND NetC217_1 NetC217_2 NetR386_1 NetR387_1 NetR557_1 NetR558_1 VREGIN
net class U20_Nets: GND NetU20_1 NetU20_3 USB_N USB_P
net class U17_Nets: GND LMX1_CSb LMX2_CSb NetR207_1 NetR218_1 NetR219_1 NetR381_1 VREGIN
net class U16_Nets: ACBUS1 F_LMK_CSb F_LMK_LMX_CLK F_LMK_LMX_DATA FMC_SPI_CLK1 FMC_SPI_CLK2 FMC_SPI_SCSb1 FMC_SPI_SCSb3 FMC_SPI_SDIO1 FMC_SPI_SDIO2 GND LMK04832-SP_RESET1 LMK04832-SP_RESET2 NetR371_2 RESET VREGIN
net class U14_Nets: GND NetR191_1 NetR191_2 NetR194_2 VDDD33
net class U11_Nets: GND NetC203_2 NetC207_2 NetC208_2 NetC210_1 NetC212_1 NetJ40_1 NetR323_1 NetR323_2 NetR326_2 NetR328_2 P4V5
net class U10_Nets: ADC_CLK3+ ADC_CLK3- ADC_SYSREF3+ ADC_SYSREF3- GND LMK_LMX_CLK LMK_LMX_DATA LMX3_CSb LMX_OSCin3+ LMX_OSCin3- MUXout3 NetC154_2 NetC155_2 NetC157_2 NetC159_1 NetC164_2 NetC165_2 NetC167_2 NetC168_1 NetC169_2 NetC170_2 NetC172_1 NetC174_1 NetC180_1 NetC182_1 NetC183_1 NetCE_TP3_1 NetR267_1 NetR268_1 NetRMPCLK3_1 NetRMPDIR3_1
net class U9_Nets: C_VCC CDCLVP_CLK1_N CDCLVP_CLK1_P CDCM7005-SP_VCXO_IN_N CDCM7005-SP_VCXO_IN_P GND NetJ30_2 NetR397_1 NetR399_1 NetR430_1 NetR432_1 NetR440_1 NetR442_1 NetR450_1 NetR452_1 NetR460_1 NetR462_1 NetR470_1 NetR472_1 NetU9_11 NetU9_12 NetU9_19 NetU9_20 NetU9_31 NetU9_32 NetU9_33 NetU9_34 VBB
net class U7_Nets: EECLK EECS EEDATA GND NetR160_1 VREGIN
net class U6_Nets: GND NetC66_2 NetC70_2 NetC73_2 NetC75_1 NetC77_1 NetJ12_1 NetR122_1 NetR122_2 NetR125_2 NetR128_2 P4V5
net class U5_Nets: ADBUS0 ADBUS1 ADBUS2 ADBUS3 ADBUS4 ADBUS5 ADBUS6 ADBUS7 D_N D_P EECLK EECS EEDATA GND NetC113_2 NetR147_1 NetR153_1 NetR217_2 NetR340_2 NetR341_2 NetU5_26 NetU5_27 NetU5_28 NetU5_29 NetU5_30 NetU5_33 OSCI OSCO USB_RESET VCCA VPHY VPLL VREGIN
net class U4_Nets: ADC_CLK2+ ADC_CLK2- ADC_SYSREF2+ ADC_SYSREF2- GND LMK_LMX_CLK LMK_LMX_DATA LMX2_CSb LMX2_OSCin+ LMX2_OSCin- MUXout2 NetC128_2 NetC129_2 NetC130_2 NetC138_2 NetC139_2 NetC140_2 NetC143_2 NetC144_1 NetC145_2 NetC146_1 NetC147_1 NetC150_2 NetC151_1 NetC152_1 NetC190_1 NetCE_TP2_1 NetR334_1 NetR342_1 NetRMPCLK2_1 NetRMPDIR2_1
net class U3_Nets: ADC_CLK1+ ADC_CLK1- ADC_SYSREF1+ ADC_SYSREF1- GND LMK_LMX_CLK LMK_LMX_DATA LMX1_CSb LMX1_OSCin+ LMX1_OSCin- MUXout1 NetC46_2 NetC47_2 NetC49_2 NetC50_2 NetC55_2 NetC56_2 NetC58_2 NetC60_1 NetC98_2 NetC99_1 NetC100_2 NetC101_1 NetC102_1 NetC103_1 NetC104_1 NetCE_TP1_1 NetR213_1 NetR214_1 NetRMPCLK1_1 NetRMPDIR1_1
net class U2_Nets: GND NetC187_2 NetR45_1 NetR46_1 NetR51_2 NetU2_1 SCL SDA
net class U1_Nets: CLKin0_N CLKin0_P CLKin1_N CLKin1_P CLKin_SEL0 CLKin_SEL1 CPout1 CPout2 DCLKout0+ DCLKout0- DCLKout2+ DCLKout2- DCLKout12+ DCLKout12- DCLKout12a_N DCLKout12a_P F_CORECLK1+ F_CORECLK1- F_CORECLK2+ F_CORECLK2- F_REFCLK1+ F_REFCLK1- F_REFCLK2+ F_REFCLK2- F_SYSREF1+ F_SYSREF1- F_SYSREF2+ F_SYSREF2- GND IOVLVL LMK04832-SP_CSb LMK_LMX_CLK LMK_LMX_DATA LMK_OSCin_N LMK_OSCin_P NetC13_2 NetC14_1 NetR282_2 NetR283_2 NetR288_2 NetR289_2 NetR292_2 NetR293_2 NetR553_2 NetR554_2 OSCout_N OSCout_P RESET SDCLKout1+ SDCLKout1- SDCLKout3+ SDCLKout3- SDCLKout13+ SDCLKout13- SDCLKout13a_N SDCLKout13a_P Status_LD1 Status_LD2 SYNC Vcc1_VCO Vcc2_CG1 Vcc3_SYSREF Vcc4_CG2 Vcc5_DIG Vcc6_PLL1 Vcc7_OSCOUT Vcc8_OSCIN Vcc9_CP2 Vcc10_PLL2 Vcc11_CG3 Vcc12_CG0
net class TP84_Nets: Vcc5_DIG
net class TP83_Nets: Vcc6_PLL1
net class TP82_Nets: GND
net class TP81_Nets: GND
net class TP80_Nets: GND
net class TP79_Nets: P4V5
net class TP78_Nets: P5V0
net class TP77_Nets: GND
net class TP76_Nets: GND
net class TP75_Nets: GND
net class TP74_Nets: GND
net class TP73_Nets: NetC343_1
net class TP72_Nets: +3.3V_CDCM7005
net class TP71_Nets: NetR536_2
net class TP70_Nets: NetR529_1
net class TP69_Nets: GND
net class TP68_Nets: PWRGD_LDO_C
net class TP67_Nets: +3.3V_VCO
net class TP66_Nets: P3V8
net class TP65_Nets: P3V3C
net class TP64_Nets: GND
net class TP63_Nets: GND
net class TP62_Nets: GND
net class TP61_Nets: GND
net class TP60_Nets: NetC303_1
net class TP59_Nets: +3.3V_LMXRF
net class TP58_Nets: NetR523_2
net class TP57_Nets: NetR516_1
net class TP56_Nets: GND
net class TP55_Nets: PWRGD_LDO_B
net class TP54_Nets: P3V3_LMX
net class TP53_Nets: P3V8
net class TP52_Nets: P3V3B
net class TP51_Nets: GND
net class TP50_Nets: GND
net class TP49_Nets: GND
net class TP48_Nets: GND
net class TP47_Nets: NetC284_1
net class TP46_Nets: VDDD33
net class TP45_Nets: NetR512_2
net class TP44_Nets: NetR504_1
net class TP43_Nets: GND
net class TP42_Nets: PWRGD_LDO_A
net class TP41_Nets: +3.3VLMK
net class TP40_Nets: P3V8
net class TP39_Nets: P3V3A
net class TP38_Nets: NetR488_2
net class TP37_Nets: NetC264_2
net class TP36_Nets: GND
net class TP35_Nets: NetC260_1
net class TP34_Nets: NetR480_2
net class TP33_Nets: NetC262_2
net class TP32_Nets: NetC258_1
net class TP31_Nets: NetC263_2
net class TP30_Nets: NetC249_1
net class TP29_Nets: NetC259_1
net class TP28_Nets: NetC250_1
net class TP27_Nets: VIN_P5V0_Redundant
net class TP26_Nets: GND
net class TP25_Nets: GND
net class TP24_Nets: GND
net class TP23_Nets: GND
net class TP22_Nets: GND
net class TP21_Nets: NetC243_1
net class TP20_Nets: NetR419_2
net class TP19_Nets: NetC246_2
net class TP18_Nets: NetC241_1
net class TP17_Nets: NetC247_2
net class TP16_Nets: NetC223_1
net class TP15_Nets: NetC242_1
net class TP14_Nets: NetC239_1
net class TP13_Nets: P3V8
net class TP12_Nets: P5V0
net class TP11_Nets: VIN_P5V0
net class TP10_Nets: NetR387_1
net class TP9_Nets: NetR386_1
net class TP8_Nets: C_VCC
net class TP5_Nets: GND
net class TP4_Nets: Vcc4_CG2
net class TP3_Nets: Vcc3_SYSREF
net class TP2_Nets: Vcc2_CG1
net class TP1_Nets: Vcc1_VCO
net class SYNC_Nets: SYNC
net class S8_Nets: NetJ47_1 VIN_P5V0_Redundant
net class S7_Nets: NetJ44_1 VIN_P5V0
net class RMPDIR3_Nets: NetRMPDIR3_1
net class RMPDIR2_Nets: NetRMPDIR2_1
net class RMPDIR1_Nets: NetRMPDIR1_1
net class RMPCLK3_Nets: NetRMPCLK3_1
net class RMPCLK2_Nets: NetRMPCLK2_1
net class RMPCLK1_Nets: NetRMPCLK1_1
net class RFoutBP3_Nets: GND RFoutB3_P
net class RFoutBP2_Nets: GND RFoutB2_P
net class RFoutBM1_Nets: GND RFoutB1_N
net class RFoutBM3_Nets: GND RFoutB3_N
net class RFoutBM2_Nets: GND RFoutB2_N
net class RFoutBP1_Nets: GND RFoutB1_P
net class RFoutAP3_Nets: GND RFoutA3_P
net class RFoutAP2_Nets: GND RFoutA2_P
net class RFoutAP1_Nets: GND RFoutA1_P
net class RFoutAM3_Nets: GND RFoutA3_N
net class RFoutAM2_Nets: GND RFoutA2_N
net class RFoutAM1_Nets: GND RFoutA1_N
net class R560_Nets: NetR558_1 SDA
net class R559_Nets: NetR557_1 SCL
net class R558_Nets: NetR558_1 VREGIN
net class R557_Nets: NetR557_1 VREGIN
net class R556_Nets: CLKin1_N CLKin1c_N
net class R555_Nets: CLKin1_P CLKin1c_P
net class R554_Nets: CLKin1c_N NetR554_2
net class R553_Nets: CLKin1c_P NetR553_2
net class R552_Nets: GND NetJ59_1
net class R551_Nets: GND NetC345_2
net class R550_Nets: NetC347_2 NetJ59_1
net class R549_Nets: NetC345_2 NetD21_1
net class R548_Nets: NetC347_1 NetC347_2
net class R547_Nets: NetC347_1 P4V5
net class R546_Nets: NetR545_1 P4V5
net class R545_Nets: NetR545_1 P5V0
net class R544_Nets: NetD20_1 VIN_P5V0_Redundant
net class R543_Nets: NetD19_1 P5V0*
net class R542_Nets: NetD18_1 P4V5
net class R541_Nets: NetD17_1 P5V0*
net class R540_Nets: NetD16_1 P5V0*
net class R539_Nets: NetD15_1 P5V0*
net class R538_Nets: NetD14_1 P5V0*
net class R537_Nets: GND NetJ53_1
net class R536_Nets: GND NetR536_2
net class R535_Nets: NetC137_2 NetJ53_1
net class R534_Nets: GND NetJ54_2
net class R533_Nets: NetC137_1 NetC137_2
net class R532_Nets: NetJ54_2 PWRGD
net class R531_Nets: P3V3C PWRGD_LDO_C
net class R530_Nets: NetC137_1 P3V3C
net class R529_Nets: NetR529_1 P3V8
net class R528_Nets: NetL28_1 P3V3C
net class R527_Nets: NetR526_1 P3V3C
net class R526_Nets: NetR526_1 P3V8
net class R525_Nets: NetL28_1 P3V3B
net class R524_Nets: GND NetJ51_1
net class R523_Nets: GND NetR523_2
net class R522_Nets: NetC136_2 NetJ51_1
net class R521_Nets: GND NetJ52_2
net class R520_Nets: NetC136_1 NetC136_2
net class R519_Nets: NetJ52_2 PWRGD
net class R518_Nets: P3V3B PWRGD_LDO_B
net class R517_Nets: NetC136_1 P3V3B
net class R516_Nets: NetR516_1 P3V8
net class R515_Nets: NetR514_1 P3V3B
net class R514_Nets: NetR514_1 P3V8
net class R513_Nets: GND NetJ49_1
net class R512_Nets: GND NetR512_2
net class R511_Nets: NetC135_2 NetJ49_1
net class R510_Nets: GND NetJ50_2
net class R509_Nets: NetC135_1 NetC135_2
net class R508_Nets: NetJ50_2 PWRGD
net class R507_Nets: P3V3A PWRGD_LDO_A
net class R506_Nets: P3V8 PWRGD
net class R505_Nets: NetC135_1 P3V3A
net class R504_Nets: NetR504_1 P3V8
net class R503_Nets: NetR502_1 P3V3A
net class R502_Nets: NetR502_1 P3V8
net class R501_Nets: GND NetR501_2
net class R500_Nets: GND NetR500_2
net class R499_Nets: GND NetR499_2
net class R498_Nets: GND NetR498_2
net class R497_Nets: GND NetR497_2
net class R496_Nets: GND NetR496_2
net class R495_Nets: GND NetR495_2
net class R494_Nets: GND NetR494_2
net class R493_Nets: GND NetR493_2
net class R492_Nets: GND NetR487_2
net class R491_Nets: GND NetR486_2
net class R490_Nets: GND NetR489_2
net class R489_Nets: NetR489_2 P5V0
net class R488_Nets: NetR488_2 P5V0
net class R487_Nets: NetR487_2 P5V0
net class R486_Nets: NetR486_2 P5V0*
net class R485_Nets: NetC261_1 NetC264_1
net class R484_Nets: RFoutB3_P SDCLKout13_LMK_N
net class R483_Nets: LMX3_RFoutB3_N RFoutB3_P
net class R482_Nets: RFoutB3_N SDCLKout13_LMK_P
net class R481_Nets: LMX3_RFoutB3_P RFoutB3_N
net class R480_Nets: GND NetR480_2
net class R479_Nets: GND NetC260_1
net class R478_Nets: LMX3_RFoutA3_N RFoutA3_N
net class R477_Nets: C4_P GND
net class R476_Nets: C4_N GND
net class R475_Nets: GND NetR472_1
net class R474_Nets: GND NetR470_1
net class R473_Nets: C4_P LMX2615-SP_1_REF_P
net class R472_Nets: NetC325_2 NetR472_1
net class R471_Nets: C4_N LMX2615-SP_1_REF_N
net class R470_Nets: NetC324_2 NetR470_1
net class R469_Nets: C4_P C_VCC
net class R468_Nets: C4_N C_VCC
net class R467_Nets: C3_N GND
net class R466_Nets: C3_P GND
net class R465_Nets: GND NetR462_1
net class R464_Nets: GND NetR460_1
net class R463_Nets: C3_N LMX2615-SP_2_REF_N
net class R462_Nets: NetC323_2 NetR462_1
net class R461_Nets: C3_P LMX2615-SP_2_REF_P
net class R460_Nets: NetC322_2 NetR460_1
net class R459_Nets: C3_N C_VCC
net class R458_Nets: C3_P C_VCC
net class R457_Nets: C2_N GND
net class R456_Nets: C2_P GND
net class R455_Nets: GND NetR452_1
net class R454_Nets: GND NetR450_1
net class R453_Nets: C2_N LMX2615-SP_3_REF_N
net class R452_Nets: NetC321_2 NetR452_1
net class R451_Nets: C2_P LMX2615-SP_3_REF_P
net class R450_Nets: NetC320_2 NetR450_1
net class R449_Nets: C2_N C_VCC
net class R448_Nets: C2_P C_VCC
net class R447_Nets: C1_N GND
net class R446_Nets: C1_P GND
net class R445_Nets: GND NetR442_1
net class R444_Nets: GND NetR440_1
net class R443_Nets: C1_N LMK_OSCin_N
net class R442_Nets: NetC319_2 NetR442_1
net class R441_Nets: C1_P LMK_OSCin_P
net class R440_Nets: NetC318_2 NetR440_1
net class R439_Nets: C1_N C_VCC
net class R438_Nets: C1_P C_VCC
net class R437_Nets: GND NetC316_1
net class R436_Nets: GND NetC317_1
net class R435_Nets: GND NetR432_1
net class R434_Nets: GND NetR430_1
net class R433_Nets: NetC316_1 Y4A_SMA
net class R432_Nets: NetC316_2 NetR432_1
net class R431_Nets: NetC317_1 Y4B_SMA
net class R430_Nets: NetC317_2 NetR430_1
net class R429_Nets: C_VCC NetC316_1
net class R428_Nets: C_VCC NetC317_1
net class R427_Nets: GND NetC259_1
net class R426_Nets: GND NetC258_1
net class R425_Nets: NetC258_1 VIN_P5V0_Redundant
net class R424_Nets: NetC259_1 VIN_P5V0_Redundant
net class R423_Nets: NetC250_1 P5V0
net class R422_Nets: VIN_P5V0 VIN_P5V0_Redundant
net class R421_Nets: GND NetC244_1
net class R420_Nets: NetC245_1 NetC248_1
net class R419_Nets: GND NetR419_2
net class R418_Nets: GND NetC243_1
net class R417_Nets: GND NetC242_1
net class R416_Nets: GND NetC241_1
net class R415_Nets: GND VSENSE
net class R414_Nets: GND NetR414_1
net class R413_Nets: NetC229_1 VSENSE
net class R412_Nets: GND NetR412_1
net class R411_Nets: NetC244_1 P5V0*
net class R410_Nets: NetC241_1 VIN_P5V0
net class R409_Nets: NetC229_1 P3V8
net class R408_Nets: NetC242_1 VIN_P5V0
net class R407_Nets: P5V0 P5V0*
net class R405_Nets: ACBUS0 VREGIN
net class R404_Nets: GND NetC132_1
net class R403_Nets: GND NetC92_1
net class R402_Nets: GND NetR399_1
net class R401_Nets: GND NetR397_1
net class R400_Nets: NetC132_1 Y5A_SMA
net class R399_Nets: NetC132_2 NetR399_1
net class R398_Nets: NetC92_1 Y5B_SMA
net class R397_Nets: NetC92_2 NetR397_1
net class R396_Nets: C_VCC NetC132_1
net class R395_Nets: C_VCC NetC92_1
net class R394_Nets: NetR148_1 NetR165_2
net class R393_Nets: DCLKout12_P NetR167_1
net class R392_Nets: NetR167_1 NetR391_2
net class R391_Nets: DCLKout12_N NetR391_2
net class R390_Nets: GND NetR390_2
net class R389_Nets: GND NetR389_2
net class R388_Nets: NetD7_2 NetR387_1
net class R387_Nets: NetR387_1 VREGIN
net class R386_Nets: NetR386_1 VREGIN
net class R385_Nets: NetC217_2 NetQ1_1
net class R384_Nets: NetC217_1 NetQ1_2
net class R383_Nets: NetJ17_1 VBUS
net class R381_Nets: LMX3_SDO NetR381_1
net class R380_Nets: GND NetC212_1
net class R379_Nets: GND NetC212_1
net class R378_Nets: NetC213_1 NetJ40_1
net class R377_Nets: NetC212_1 P4V5
net class R376_Nets: GND NetC210_1
net class R375_Nets: GND NetC208_2
net class R374_Nets: NetC206_1 NetL32_1
net class R373_Nets: NetC133_2 NetC203_1
net class R372_Nets: +3.3V_LMXRF NetC154_2
net class R371_Nets: GND NetR371_2
net class R370_Nets: ACBUS1 VREGIN
net class R366_Nets: GND NetR58_1
net class R364_Nets: NetC325_2 NetR364_2
net class R363_Nets: NetC322_2 NetR363_2
net class R362_Nets: LMK_VCXO NetR362_2
net class R361_Nets: NetC320_2 NetR361_2
net class R360_Nets: J26 NetR342_1
net class R359_Nets: LMX2_SYNC NetR342_1
net class R358_Nets: J24 NetR334_1
net class R357_Nets: SDCLKout13_N SDCLKout13b_N
net class R356_Nets: SDCLKout13- SDCLKout13a_N SDCLKout13b_N
net class R355_Nets: LMX2_SYSREFREQ NetR334_1
net class R354_Nets: NetC195_1 NetR350_1
net class R353_Nets: NetR350_1 OSCin2_N
net class R352_Nets: LMX2615-SP_2_REF_N NetR350_1
net class R351_Nets: GND NetR350_1
net class R350_Nets: DCLKout2*_N NetR350_1
net class R349_Nets: NetC191_1 NetC195_1
net class R348_Nets: GND NetR325_1
net class R347_Nets: RFoutB2_P SDCLKout3_LMK_P
net class R346_Nets: +3.3VLMK NetR58_1
net class R345_Nets: GND NetR11_1
net class R344_Nets: +3.3VLMK NetR11_1
net class R343_Nets: +3.3VLMK RESET
net class R342_Nets: GND NetR342_1
net class R341_Nets: ACBUS1 NetR341_2
net class R340_Nets: ACBUS0 NetR340_2
net class R339_Nets: GND NetR21_1
net class R338_Nets: +3.3VLMK NetR21_1
net class R337_Nets: GND NetR13_1
net class R336_Nets: +3.3VLMK NetR13_1
net class R335_Nets: GND IOVLVL
net class R334_Nets: GND NetR334_1
net class R333_Nets: NetC191_1 NetR325_1
net class R332_Nets: NetR325_1 OSCin2_P
net class R331_Nets: LMX2615-SP_2_REF_P NetR325_1
net class R330_Nets: GND LMX3_RFoutA3_N
net class R329_Nets: GND LMX3_RFoutA3_P
net class R328_Nets: NetR326_2 NetR328_2
net class R327_Nets: ADC_SYSREF2- NetC189_2
net class R326_Nets: NetC204_1 NetR326_2
net class R325_Nets: DCLKout2*_P NetR325_1
net class R324_Nets: NetC202_1 NetR323_1
net class R323_Nets: NetR323_1 NetR323_2
net class R322_Nets: GND NetC146_2
net class R321_Nets: NetC149_1 NetC150_2
net class R320_Nets: NetC146_1 NetC149_1
net class R319_Nets: LMX2615-SP_3_REF_N NetR301_1
net class R318_Nets: GND NetR301_1
net class R317_Nets: NetC194_1 NetR301_1
net class R316_Nets: NetOSCinM3_1 NetR301_1
net class R315_Nets: ADC_SYSREF2+ NetC189_2
net class R314_Nets: MUXout2 NetD6_1
net class R313_Nets: LMX2_SDO MUXout2
net class R312_Nets: LMX3_SCSb VREGIN
net class R311_Nets: R_ELMK_SDO RESET
net class R310_Nets: LMX2_SCSb VREGIN
net class R309_Nets: LMX1_SCSb VREGIN
net class R308_Nets: LMK_SCSb VREGIN
net class R307_Nets: CLKin_SEL1 NetJ19_7
net class R306_Nets: NetJ19_1 SYNC
net class R305_Nets: ELMK_SDO R_ELMK_SDO
net class R304_Nets: GND NetJ19_6
net class R303_Nets: ELMK_SDIO NetJ19_4
net class R302_Nets: ELMK_SCK NetJ19_8
net class R301_Nets: DCLKout12*_N NetR301_1
net class R300_Nets: NetC193_1 NetC194_1
net class R299_Nets: GND NetC89_2
net class R298_Nets: GND NetR49_1
net class R297_Nets: GND NetR29_1
net class R296_Nets: CLKin_SEL0 E_SDA
net class R295_Nets: DCLKout12*_P NetR272_1
net class R294_Nets: MUXout3 NetD13_1
net class R293_Nets: NetR293_2 SDCLKout5*_N SDCLKout5-
net class R292_Nets: NetR292_2 SDCLKout5*_P SDCLKout5+
net class R291_Nets: GND NetR47_1
net class R290_Nets: +3.3VLMK NetR29_1
net class R289_Nets: NetR42_1 NetR289_2 SDCLKout3- SDCLKout3-*
net class R288_Nets: NetR41_1 NetR288_2 SDCLKout3+ SDCLKout3+*
net class R287_Nets: SDCLKout1- SDCLKout1-*
net class R286_Nets: SDCLKout1+ SDCLKout1+*
net class R285_Nets: GND NetR31_1
net class R284_Nets: +3.3VLMK NetR31_1
net class R283_Nets: NetR283_2 SDCLKout11+ SDCLKout11a_P
net class R282_Nets: NetR282_2 SDCLKout11- SDCLKout11a_N
net class R281_Nets: NetC193_1 NetR272_1
net class R280_Nets: NetOSCinP3_1 NetR272_1
net class R279_Nets: LMX3_SDO MUXout3
net class R278_Nets: NetJ38_1 NetR267_1
net class R277_Nets: GND NetR272_1
net class R276_Nets: RFoutB2_N SDCLKout3_LMK_N
net class R275_Nets: DCLKout2_LMK_N RFoutA2_N
net class R274_Nets: NetCE_TP2_1 P3V3_LMX
net class R273_Nets: LMX3_SYNC NetR267_1
net class R272_Nets: LMX2615-SP_3_REF_P NetR272_1
net class R271_Nets: NetJ37_1 NetR268_1
net class R270_Nets: GND NetC88_2
net class R269_Nets: LMX3_SYSREFREQ NetR268_1
net class R268_Nets: GND NetR268_1
net class R267_Nets: GND NetR267_1
net class R266_Nets: LMX3_RFoutA3_P RFoutA3_P
net class R265_Nets: ADC_SYSREF3- NetC173_2
net class R264_Nets: GND NetC172_2
net class R263_Nets: NetC170_2 NetC171_1
net class R262_Nets: NetC171_1 NetC172_1
net class R261_Nets: ADC_SYSREF3+ NetC173_2
net class R260_Nets: ADC_CLK2- NetC131_2
net class R259_Nets: NetC165_2 P3V3_LMX
net class R258_Nets: ADC_CLK2+ NetC131_2
net class R257_Nets: NetC129_2 P3V3_LMX
net class R256_Nets: NetC130_2 P3V3_LMX
net class R255_Nets: NetC138_2 P3V3_LMX
net class R254_Nets: NetC139_2 P3V3_LMX
net class R253_Nets: NetC128_2 P3V3_LMX
net class R252_Nets: +3.3V_LMXRF NetC140_2
net class R251_Nets: NetC140_2 P3V3_LMX
net class R250_Nets: NetCE_TP3_1 P3V3_LMX
net class R249_Nets: J22 NetR214_1
net class R248_Nets: DCLKout2_LMK_P RFoutA2_P
net class R247_Nets: LMX1_SYNC NetR214_1
net class R246_Nets: J21 NetR213_1
net class R245_Nets: LMX1_SYSREFREQ NetR213_1
net class R244_Nets: NetR112_2 OSCin1_N
net class R243_Nets: LMX2615-SP_1_REF_N NetR112_2
net class R242_Nets: DCLKout0*_N NetR112_2
net class R241_Nets: RFoutB1_P SDCLKout1_LMK_P
net class R240_Nets: NetR104_1 OSCin1_P
net class R239_Nets: LMX2615-SP_1_REF_P NetR104_1
net class R238_Nets: DCLKout0*_P NetR104_1
net class R237_Nets: RFoutB1_N SDCLKout1_LMK_N
net class R236_Nets: DCLKout0_LMK_N RFoutA1_N
net class R235_Nets: +3.3V_LMXRF NetC50_2
net class R234_Nets: DCLKout0_LMK_P RFoutA1_P
net class R233_Nets: NetR215_1 SDCLKout3_P
net class R232_Nets: NetC164_2 P3V3_LMX
net class R231_Nets: NetC159_1 P3V3_LMX
net class R230_Nets: ADC_CLK3- NetC156_2
net class R229_Nets: DCLKout12_LMK_N RFoutA3_N
net class R228_Nets: NetC157_2 P3V3_LMX
net class R227_Nets: NetC155_2 P3V3_LMX
net class R226_Nets: NetC154_2 P3V3_LMX
net class R225_Nets: F_LMX2_SDO LMX2_SDO
net class R224_Nets: ADC_CLK3+ NetC156_2
net class R223_Nets: DCLKout12_LMK_P RFoutA3_P
net class R220_Nets: CDCLVP_CLK1_N NetC89_2
net class R219_Nets: LMX2_SDO NetR219_1
net class R218_Nets: LMX1_SDO NetR218_1
net class R217_Nets: NetD10_1 NetR217_2
net class R216_Nets: LMX2_SYSREFREQ NetR208_1
net class R215_Nets: NetR208_1 NetR215_1
net class R214_Nets: GND NetR214_1
net class R213_Nets: GND NetR213_1
net class R212_Nets: ADBUS2 SDA
net class R211_Nets: E_SCL IOVLVL
net class R210_Nets: NetC318_2 NetR210_2
net class R209_Nets: LMX2_SYNC SDCLKout5_P
net class R208_Nets: NetR208_1 SDCLKout3_N
net class R207_Nets: LMX_SDO NetR207_1
net class R206_Nets: FMC_SPI_SCSb4 ILMX2_CSb
net class R205_Nets: ADBUS7 VREGIN
net class R204_Nets: SDCLKout5_N SDCLKout5_P
net class R203_Nets: NetR169_1 SDCLKout1_P
net class R202_Nets: LMK04832-SP_SYNC2 SYNC
net class R201_Nets: NetR193_2 SYNC
net class R200_Nets: LMK04832-SP_SYNC1 SYNC
net class R199_Nets: +3.3VLMK OSCin-
net class R198_Nets: +3.3VLMK OSCin+
net class R197_Nets: NetR193_2 SYNC2_OUT
net class R196_Nets: NetR193_2 SYNC1_OUT
net class R195_Nets: NetR191_1 NetR194_2
net class R194_Nets: NetR194_2 SYNC2_IN
net class R193_Nets: NetR191_1 NetR193_2
net class R192_Nets: NetR191_2 SYNC1_IN
net class R191_Nets: NetR191_1 NetR191_2
net class R190_Nets: +3.3VLMK SYNC
net class R189_Nets: F_LMX1_SDO LMX1_SDO
net class R188_Nets: FMC_SPI_SCSb2 ILMX1_CSb
net class R187_Nets: F_LMK_CSb ILMK04832-SP_CSb
net class R186_Nets: F_LMK_LMX_DATA ILMK_LMX_DATA
net class R185_Nets: F_LMK_LMX_CLK ILMK_LMX_CLK
net class R184_Nets: F_CORECLK2+ F_CORECLK2_P
net class R183_Nets: F_CORECLK2- F_CORECLK2_N
net class R182_Nets: F_CORECLK1+ F_CORECLK1_P
net class R181_Nets: ADBUS7 ILMX2_CSb
net class R180_Nets: CDCLVP_CLK1_P NetC88_2
net class R179_Nets: +3.3VLMK NetC89_2
net class R178_Nets: ADBUS0 SCL
net class R177_Nets: +3.3VLMK NetC88_2
net class R175_Nets: C_VCC NetJ30_1
net class R173_Nets: E_SDA SDA
net class R172_Nets: E_SCL SCL
net class R171_Nets: GND NetC87_1
net class R170_Nets: NetC86_2 NetC87_1
net class R169_Nets: NetR142_1 NetR169_1
net class R168_Nets: NetR146_2 NetR165_2
net class R167_Nets: NetR144_1 NetR167_1
net class R166_Nets: NetR142_1 SDCLKout1_N
net class R165_Nets: NetR165_2 SDCLKout13_P
net class R164_Nets: NetR106_2 NetR111_1
net class R163_Nets: EEDATA NetR160_1
net class R162_Nets: EECLK VREGIN
net class R161_Nets: EECS VREGIN
net class R160_Nets: NetR160_1 VREGIN
net class R159_Nets: ADBUS6 ILMX_SDO
net class R158_Nets: ADBUS5 ILMX1_CSb
net class R157_Nets: ADBUS4 ILMK04832-SP_CSb
net class R156_Nets: ADBUS3 ILMK_LMX_DATA
net class R155_Nets: USB_RESET VBUS
net class R154_Nets: ADBUS1 ILMK_LMX_CLK
net class R153_Nets: GND NetR153_1
net class R152_Nets: ADBUS5 VREGIN
net class R151_Nets: ADBUS4 VREGIN
net class R150_Nets: D_P USB_P
net class R149_Nets: D_N USB_N
net class R148_Nets: LMX3_SYSREFREQ NetR148_1
net class R147_Nets: NetR147_1 VBUS
net class R146_Nets: NetR146_2 SDCLKout13_N
net class R145_Nets: CLKin1c_N CLKin1c_P
net class R144_Nets: LMX3_SYNC NetR144_1
net class R143_Nets: SDCLKout11_N SDCLKout11_P
net class R142_Nets: LMX1_SYSREFREQ NetR142_1
net class R141_Nets: LMX1_SYNC SDCLKout11_P
net class R140_Nets: GND NetC77_1
net class R139_Nets: GND NetC77_1
net class R138_Nets: NetC78_1 NetJ12_1
net class R137_Nets: NetC77_1 P4V5
net class R136_Nets: SDCLKout13_LMK_N SDCLKout13_N
net class R135_Nets: SDCLKout13_LMK_P SDCLKout13_P
net class R134_Nets: GND NetC75_1
net class R133_Nets: GND NetC73_2
net class R132_Nets: DCLKout12*_N DCLKout12_N
net class R131_Nets: CLKin1d_N NetC68_1
net class R130_Nets: DCLKout12_LMK_N DCLKout12_N
net class R129_Nets: GND NetC69_2
net class R128_Nets: NetR125_2 NetR128_2
net class R127_Nets: DCLKout12*_P DCLKout12_P
net class R126_Nets: DCLKout12_LMK_P DCLKout12_P
net class R125_Nets: NetC69_1 NetR125_2
net class R124_Nets: NetC65_1 NetR122_1
net class R123_Nets: GND NetC65_2
net class R122_Nets: NetR122_1 NetR122_2
net class R121_Nets: CLKin1d_P NetC66_1
net class R120_Nets: NetC39_1 NetR116_1
net class R119_Nets: GND NetC39_1
net class R118_Nets: GND NetR116_1
net class R117_Nets: NetR116_1 NetR117_1
net class R116_Nets: NetR103_1 NetR116_1
net class R115_Nets: +3.3VLMK NetR49_1
net class R114_Nets: +3.3VLMK NetR47_1
net class R113_Nets: GND NetR112_2
net class R112_Nets: NetC72_1 NetR112_2
net class R111_Nets: NetR103_1 NetR111_1
net class R110_Nets: GND NetC38_1
net class R109_Nets: NetC71_1 NetC72_1
net class R108_Nets: GND NetR103_1
net class R107_Nets: NetC71_1 NetR104_1
net class R106_Nets: NetJ5_1 NetR106_2
net class R105_Nets: MUXout1 NetD5_1
net class R104_Nets: GND NetR104_1
net class R103_Nets: NetC38_1 NetR103_1
net class R102_Nets: LMX1_SDO MUXout1
net class R101_Nets: CLKINN0 CLKINN1
net class R100_Nets: CLKINN0 GND
net class R99_Nets: CLKINP0 GND
net class R98_Nets: CLKINP0 CLKINP1
net class R97_Nets: ADC_SYSREF1- NetC61_1
net class R96_Nets: GND NetC60_2
net class R95_Nets: NetC59_1 NetC60_1
net class R94_Nets: NetC58_2 NetC59_1
net class R93_Nets: ADC_SYSREF1+ NetC61_1
net class R92_Nets: SDCLKout3_LMK_N SDCLKout3_N
net class R91_Nets: NetC46_2 P3V3_LMX
net class R90_Nets: NetCE_TP1_1 P3V3_LMX
net class R89_Nets: NetC47_2 P3V3_LMX
net class R88_Nets: NetC49_2 P3V3_LMX
net class R87_Nets: NetC50_2 P3V3_LMX
net class R86_Nets: ADC_CLK1- NetC45_1
net class R85_Nets: NetC55_2 P3V3_LMX
net class R84_Nets: SDCLKout3_LMK_P SDCLKout3_P
net class R83_Nets: NetC56_2 P3V3_LMX
net class R82_Nets: ADC_CLK1+ NetC45_1
net class R81_Nets: DCLKout2*_N DCLKout2_N
net class R80_Nets: NetD4_1 Status_LD2
net class R79_Nets: NetD3_1 Status_LD1
net class R78_Nets: CLKin_SEL0 NetD2_1
net class R77_Nets: CLKin_SEL1 NetD1_1
net class R76_Nets: DCLKout2_LMK_N DCLKout2_N
net class R75_Nets: DCLKout2*_P DCLKout2_P
net class R74_Nets: DCLKout2_LMK_P DCLKout2_P
net class R73_Nets: SDCLKout1_LMK_N SDCLKout1_N
net class R72_Nets: SDCLKout1_LMK_P SDCLKout1_P
net class R71_Nets: DCLKout0*_N DCLKout0_N
net class R70_Nets: F_CORECLK1- F_CORECLK1_N
net class R69_Nets: DCLKout0_LMK_N DCLKout0_N
net class R68_Nets: DCLKout0*_P DCLKout0_P
net class R67_Nets: F_CORECLK2+ GND
net class R66_Nets: F_CORECLK2- GND
net class R65_Nets: F_REFCLK2+ GND
net class R64_Nets: F_REFCLK2- GND
net class R63_Nets: F_REFCLK2- F_REFCLK2_N
net class R62_Nets: F_REFCLK2+ F_REFCLK2_P
net class R61_Nets: F_SYSREF2+ GND
net class R60_Nets: F_SYSREF2- GND
net class R59_Nets: NetR58_1 SDCLKout5*_P SDCLKout5+
net class R58_Nets: NetR58_1 SDCLKout5*_N SDCLKout5-
net class R57_Nets: F_SYSREF2+ F_SYSREF2_P
net class R56_Nets: J15J13_N SDCLKout5*_N SDCLKout5-
net class R55_Nets: F_SYSREF2- F_SYSREF2_N
net class R54_Nets: J15J13_P SDCLKout5*_P SDCLKout5+
net class R53_Nets: GND Status_LD1
net class R52_Nets: GND NetC17_2
net class R51_Nets: +3.3V_VCO NetR51_2
net class R50_Nets: NetR41_1 NetR49_1 SDCLKout3+*
net class R49_Nets: NetR42_1 NetR49_1 SDCLKout3-*
net class R48_Nets: DCLKout2+ NetR47_1
net class R47_Nets: DCLKout2- NetR47_1
net class R46_Nets: LMK6_OUT_N NetR46_1
net class R45_Nets: LMK6_OUT_P NetR45_1
net class R44_Nets: +3.3V_VCO SCL
net class R43_Nets: +3.3V_VCO SDA
net class R42_Nets: NetR42_1 SDCLKout3-* SDCLKout3_N
net class R41_Nets: NetR41_1 SDCLKout3+* SDCLKout3_P
net class R40_Nets: GND OSCin+
net class R39_Nets: LMK_VCXO NetOSCinP_1
net class R38_Nets: CDCM7005-SP_VCXO_IN_P OSCin+
net class R37_Nets: NetC9_1 NetOSCinN_1
net class R36_Nets: CDCM7005-SP_VCXO_IN_N OSCin-
net class R35_Nets: GND RESET
net class R34_Nets: GND OSCin-
net class R33_Nets: CPout1 NetR33_1
net class R32_Nets: DCLKout0+ NetR31_1
net class R31_Nets: DCLKout0- NetR31_1
net class R30_Nets: NetR29_1 SDCLKout1+*
net class R29_Nets: NetR29_1 SDCLKout1-*
net class R28_Nets: GND NetC8_1
net class R27_Nets: SDCLKout1-* SDCLKout1_N
net class R26_Nets: DCLKout0_LMK_P DCLKout0_P
net class R25_Nets: SDCLKout1+* SDCLKout1_P
net class R24_Nets: F_SYSREF1+ GND
net class R23_Nets: F_SYSREF1- GND
net class R22_Nets: DCLKout12+ DCLKout12a_P NetR21_1
net class R21_Nets: DCLKout12- DCLKout12a_N NetR21_1
net class R20_Nets: F_SYSREF1+ F_SYSREF1_P
net class R19_Nets: F_SYSREF1- F_SYSREF1_N
net class R18_Nets: F_CORECLK1+ GND
net class R17_Nets: F_CORECLK1- GND
net class R16_Nets: F_REFCLK1+ GND
net class R15_Nets: F_REFCLK1- GND
net class R14_Nets: NetR13_1 SDCLKout13b_P
net class R13_Nets: NetR13_1 SDCLKout13b_N
net class R12_Nets: NetR11_1 SDCLKout11+ SDCLKout11a_P
net class R11_Nets: NetR11_1 SDCLKout11- SDCLKout11a_N
net class R10_Nets: SDCLKout5*_N SDCLKout5- SDCLKout5_N
net class R9_Nets: SDCLKout11- SDCLKout11_N SDCLKout11a_N
net class R8_Nets: SDCLKout13_P SDCLKout13b_P
net class R7_Nets: F_REFCLK1+ F_REFCLK1_P
net class R6_Nets: J1J4_N SDCLKout11- SDCLKout11a_N
net class R5_Nets: SDCLKout13+ SDCLKout13a_P SDCLKout13b_P
net class R4_Nets: F_REFCLK1- F_REFCLK1_N
net class R3_Nets: J1J4_P SDCLKout11+ SDCLKout11a_P
net class R2_Nets: SDCLKout5*_P SDCLKout5+ SDCLKout5_P
net class R1_Nets: SDCLKout11+ SDCLKout11_P SDCLKout11a_P
net class Q1_Nets: GND NetQ1_1 NetQ1_2
net class OSCinP_Nets: GND NetOSCinP_1
net class OSCinP3_Nets: GND NetOSCinP3_1
net class OSCinP2_Nets: GND OSCin2_P
net class OSCinP1_Nets: GND OSCin1_P
net class OSCinN_Nets: GND NetOSCinN_1
net class OSCinM3_Nets: GND NetOSCinM3_1
net class OSCinM2_Nets: GND OSCin2_N
net class OSCinM1_Nets: GND OSCin1_N
net class L40_Nets: NetC134_1 NetC331_1
net class L39_Nets: NetC105_1 NetC332_2
net class L38_Nets: NetC331_2 NetC333_1
net class L37_Nets: NetC105_2 NetC332_1
net class L32_Nets: NetC332_2 NetL32_1
net class L31_Nets: Vcc1_VCO Vcc6_PLL1
net class L30_Nets: Vcc1_VCO Vcc5_DIG
net class L29_Nets: +3.3V_CDCM7005 NetL28_1
net class L28_Nets: +3.3V_VCO NetL28_1
net class L27_Nets: +3.3V_LMXRF P3V3B
net class L26_Nets: P3V3_LMX P3V3B
net class L25_Nets: P3V3A VDDD33
net class L24_Nets: +3.3VLMK P3V3A
net class L23_Nets: NetD12_1 P3V8
net class L22_Nets: +3.3V_LMXRF NetC173_2
net class L21_Nets: +3.3V_LMXRF NetC156_2
net class L19_Nets: +3.3V_LMXRF NetC189_2
net class L18_Nets: +3.3V_LMXRF NetC131_2
net class L17_Nets: +3.3V_CDCM7005 C_VCC
net class L16_Nets: VPLL VREGIN
net class L15_Nets: VPHY VREGIN
net class L14_Nets: LMX3_RFoutB3_P NetC331_2
net class L13_Nets: NetC19_2 NetJ8_1
net class L12_Nets: +3.3V_LMXRF NetC61_1
net class L11_Nets: +3.3V_LMXRF NetC45_1
net class L10_Nets: +3.3VLMK Vcc12_CG0
net class L9_Nets: +3.3VLMK Vcc11_CG3
net class L8_Nets: +3.3VLMK Vcc4_CG2
net class L7_Nets: +3.3VLMK Vcc3_SYSREF
net class L6_Nets: Vcc9_CP2 Vcc10_PLL2
net class L5_Nets: +3.3VLMK Vcc10_PLL2
net class L4_Nets: +3.3VLMK Vcc2_CG1
net class L3_Nets: Vcc8_OSCIN Vcc10_PLL2
net class L2_Nets: +3.3VLMK Vcc1_VCO
net class L1_Nets: Vcc7_OSCOUT Vcc10_PLL2
net class J59_Nets: NetC347_1 NetJ59_1
net class J58_Nets: GND NetC333_1
net class J57_Nets: GND NetC332_1
net class J56_Nets: GND NetJ56_2 P5V0
net class J55_Nets: GND NetC331_1
net class J54_Nets: GND NetJ54_2
net class J53_Nets: NetC137_1 NetJ53_1
net class J52_Nets: GND NetJ52_2
net class J51_Nets: NetC136_1 NetJ51_1
net class J50_Nets: GND NetJ50_2
net class J49_Nets: NetC135_1 NetJ49_1
net class J48_Nets: GND NetC259_1 VIN_P5V0_Redundant
net class J47_Nets: GND NetJ47_1
net class J46_Nets: NetC262_2 VIN_P5V0_Redundant
net class J45_Nets: GND NetC242_1 VIN_P5V0
net class J44_Nets: GND NetJ44_1
net class J43_Nets: NetC246_2 VIN_P5V0
net class J42_Nets: GND NetC212_1
net class J41_Nets: GND NetJ40_1
net class J40_Nets: NetJ40_1 P4V5
net class J39_Nets: ACBUS1 GND
net class J38_Nets: GND NetJ38_1
net class J37_Nets: GND NetJ37_1
net class J33_Nets: F_CORECLK2_N F_CORECLK2_P F_LMX2_SDO F_REFCLK2_N F_REFCLK2_P F_SYSREF2_N F_SYSREF2_P FMC_SPI_CLK2 FMC_SPI_SCSb3 FMC_SPI_SCSb4 FMC_SPI_SDIO2 GND LMK04832-SP_RESET2 LMK04832-SP_SYNC2 NetJ33_1 NetJ33_4 NetJ33_6 NetJ33_12 NetJ33_14 NetJ33_20 NetJ33_22 NetJ33_28 NetJ33_30 NetJ33_36 NetJ33_38 NetJ33_44 NetJ33_46 NetJ33_52 NetJ33_54 SYNC2_IN SYNC2_OUT
net class J32_Nets: F_CORECLK1_N F_CORECLK1_P F_LMX1_SDO F_REFCLK1_N F_REFCLK1_P F_SYSREF1_N F_SYSREF1_P FMC_SPI_CLK1 FMC_SPI_SCSb1 FMC_SPI_SCSb2 FMC_SPI_SDIO1 GND LMK04832-SP_RESET1 LMK04832-SP_SYNC1 NetJ32_1 NetJ32_4 NetJ32_6 NetJ32_12 NetJ32_14 NetJ32_20 NetJ32_22 NetJ32_28 NetJ32_30 NetJ32_36 NetJ32_38 NetJ32_44 NetJ32_46 NetJ32_52 NetJ32_54 SYNC1_IN SYNC1_OUT
net class J30_Nets: GND NetJ30_1 NetJ30_2
net class J27_Nets: GND Y5A_SMA
net class J26_Nets: GND J26
net class J25_Nets: GND Y5B_SMA
net class J24_Nets: GND J24
net class J22_Nets: GND J22
net class J21_Nets: GND J21
net class J20_Nets: ACBUS0 ELMK_CS GND LMK_SCSb LMX1_SCSb LMX2_SCSb LMX3_SCSb NetJ20_11 NetJ20_12 NetJ20_13 NetJ20_14 NetJ20_15 NetJ20_16 NetJ20_17 NetJ20_18 NetJ20_19 NetJ20_20
net class J19_Nets: E_SCL E_SDA ELMK_CS NetJ19_1 NetJ19_4 NetJ19_5 NetJ19_6 NetJ19_7 NetJ19_8 R_ELMK_SDO
net class J18_Nets: GND NetC77_1
net class J17_Nets: GND NetJ17_1 NetJ17_4 USB_N USB_P
net class J16_Nets: +3.3V_VCO NetC187_2
net class J15_Nets: GND J15J13_P
net class J14_Nets: GND NetJ12_1
net class J13_Nets: GND J15J13_N
net class J12_Nets: NetJ12_1 P4V5
net class J11_Nets: GND NetC105_1
net class J10_Nets: GND NetC69_2
net class J9_Nets: GND Y4A_SMA
net class J8_Nets: +3.3V_VCO NetJ8_1
net class J7_Nets: GND Y4B_SMA
net class J6_Nets: GND NetC65_2
net class J5_Nets: GND NetJ5_1
net class J4_Nets: GND J1J4_N
net class J3_Nets: CLKINN0 GND
net class J2_Nets: CLKINP0 GND
net class J1_Nets: GND J1J4_P
net class D22_Nets: GND NetC345_2
net class D21_Nets: NetC347_2 NetD21_1
net class D20_Nets: GND NetD20_1
net class D19_Nets: GND NetD19_1
net class D18_Nets: GND NetD18_1
net class D17_Nets: NetD17_1 NetD17_2
net class D16_Nets: NetD16_1 NetD16_2
net class D15_Nets: NetD15_1 NetD15_2
net class D14_Nets: NetD14_1 NetD14_2
net class D13_Nets: GND NetD13_1
net class D12_Nets: GND NetD12_1
net class D10_Nets: GND NetD10_1
net class D7_Nets: NetD7_2 VREGIN
net class D6_Nets: GND NetD6_1
net class D5_Nets: GND NetD5_1
net class D4_Nets: GND NetD4_1
net class D3_Nets: GND NetD3_1
net class D2_Nets: GND NetD2_1
net class D1_Nets: GND NetD1_1
net class CE_TP3_Nets: NetCE_TP3_1
net class CE_TP2_Nets: NetCE_TP2_1
net class CE_TP1_Nets: NetCE_TP1_1
net class C356_Nets: GND Vcc6_PLL1
net class C355_Nets: GND Vcc5_DIG
net class C354_Nets: GND P5V0
net class C353_Nets: GND P5V0
net class C352_Nets: GND P5V0
net class C351_Nets: GND P5V0
net class C350_Nets: GND P4V5
net class C349_Nets: GND P4V5
net class C348_Nets: GND P4V5
net class C347_Nets: NetC347_1 NetC347_2
net class C346_Nets: GND P4V5
net class C345_Nets: NetC345_2 P4V5
net class C344_Nets: GND NetC137_2
net class C343_Nets: GND NetC343_1
net class C342_Nets: +3.3V_CDCM7005 GND
net class C341_Nets: +3.3V_CDCM7005 GND
net class C340_Nets: +3.3V_CDCM7005 GND
net class C339_Nets: +3.3V_CDCM7005 GND
net class C337_Nets: GND VDDD33
net class C335_Nets: GND VDDD33
net class C334_Nets: GND P3V3C
net class C333_Nets: NetC134_1 NetC333_1
net class C332_Nets: NetC332_1 NetC332_2
net class C331_Nets: NetC331_1 NetC331_2
net class C329_Nets: GND VDDD33
net class C328_Nets: GND VDDD33
net class C327_Nets: GND VDDD33
net class C326_Nets: GND P3V3C
net class C325_Nets: C4_P NetC325_2
net class C324_Nets: C4_N NetC324_2
net class C323_Nets: C3_N NetC323_2
net class C322_Nets: C3_P NetC322_2
net class C321_Nets: C2_N NetC321_2
net class C320_Nets: C2_P NetC320_2
net class C319_Nets: C1_N NetC319_2
net class C318_Nets: C1_P NetC318_2
net class C317_Nets: NetC317_1 NetC317_2
net class C316_Nets: NetC316_1 NetC316_2
net class C315_Nets: GND P3V3C
net class C314_Nets: GND P3V8
net class C313_Nets: GND P3V8
net class C312_Nets: GND P3V3C
net class C311_Nets: GND P3V8
net class C310_Nets: GND P3V8
net class C309_Nets: NetC309_1 P3V3C
net class C308_Nets: +3.3V_VCO GND
net class C307_Nets: +3.3V_VCO GND
net class C306_Nets: +3.3V_VCO GND
net class C305_Nets: +3.3V_VCO GND
net class C304_Nets: GND NetC136_2
net class C303_Nets: GND NetC303_1
net class C302_Nets: +3.3V_LMXRF GND
net class C301_Nets: +3.3V_LMXRF GND
net class C300_Nets: +3.3V_LMXRF GND
net class C299_Nets: +3.3V_LMXRF GND
net class C298_Nets: GND P3V3B
net class C297_Nets: GND P3V3B
net class C296_Nets: GND P3V3B
net class C295_Nets: GND P3V8
net class C294_Nets: GND P3V8
net class C293_Nets: GND P3V3B
net class C292_Nets: GND P3V8
net class C291_Nets: GND P3V8
net class C290_Nets: NetC290_1 P3V3B
net class C289_Nets: GND P3V3_LMX
net class C288_Nets: GND P3V3_LMX
net class C287_Nets: GND P3V3_LMX
net class C286_Nets: GND P3V3_LMX
net class C285_Nets: GND NetC135_2
net class C284_Nets: GND NetC284_1
net class C283_Nets: GND VDDD33
net class C282_Nets: GND VDDD33
net class C281_Nets: GND VDDD33
net class C280_Nets: GND VDDD33
net class C279_Nets: GND P3V3A
net class C278_Nets: GND P3V3A
net class C277_Nets: GND P3V3A
net class C276_Nets: GND P3V8
net class C275_Nets: GND P3V8
net class C274_Nets: GND P3V3A
net class C273_Nets: GND P3V8
net class C272_Nets: GND P3V8
net class C271_Nets: NetC271_1 P3V3A
net class C270_Nets: +3.3VLMK GND
net class C269_Nets: +3.3VLMK GND
net class C268_Nets: +3.3VLMK GND
net class C267_Nets: +3.3VLMK GND
net class C266_Nets: GND P5V0
net class C265_Nets: GND P5V0
net class C264_Nets: NetC264_1 NetC264_2
net class C263_Nets: GND NetC263_2
net class C262_Nets: GND NetC262_2
net class C261_Nets: GND NetC261_1
net class C260_Nets: GND NetC260_1
net class C259_Nets: GND NetC259_1
net class C258_Nets: GND NetC258_1
net class C257_Nets: GND VIN_P5V0_Redundant
net class C256_Nets: GND VIN_P5V0_Redundant
net class C255_Nets: GND VIN_P5V0_Redundant
net class C254_Nets: GND NetC250_1
net class C253_Nets: GND NetC250_1
net class C252_Nets: GND NetC250_1
net class C251_Nets: NetC249_1 NetC250_1
net class C250_Nets: NetC249_1 NetC250_1
net class C249_Nets: NetC249_1 VIN_P5V0_Redundant
net class C248_Nets: GND NetC248_1
net class C247_Nets: GND NetC247_2
net class C246_Nets: GND NetC246_2
net class C245_Nets: GND NetC245_1
net class C244_Nets: GND NetC244_1
net class C243_Nets: GND NetC243_1
net class C242_Nets: GND NetC242_1
net class C241_Nets: GND NetC241_1
net class C240_Nets: GND P5V0
net class C239_Nets: GND NetC239_1
net class C238_Nets: GND P5V0
net class C237_Nets: GND P5V0
net class C236_Nets: GND P5V0*
net class C235_Nets: GND P5V0*
net class C234_Nets: GND VIN_P5V0
net class C233_Nets: GND P5V0*
net class C232_Nets: GND P3V8
net class C231_Nets: GND P3V8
